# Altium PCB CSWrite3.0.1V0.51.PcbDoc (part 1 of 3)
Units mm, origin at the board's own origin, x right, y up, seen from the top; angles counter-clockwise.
Board outline 100 x 80 mm, 4 copper layers (Top Layer, power, gnd, Bottom Layer), stack 0.778 mm thick; 246 components, 181 nets, 873 pads, 864 vias.
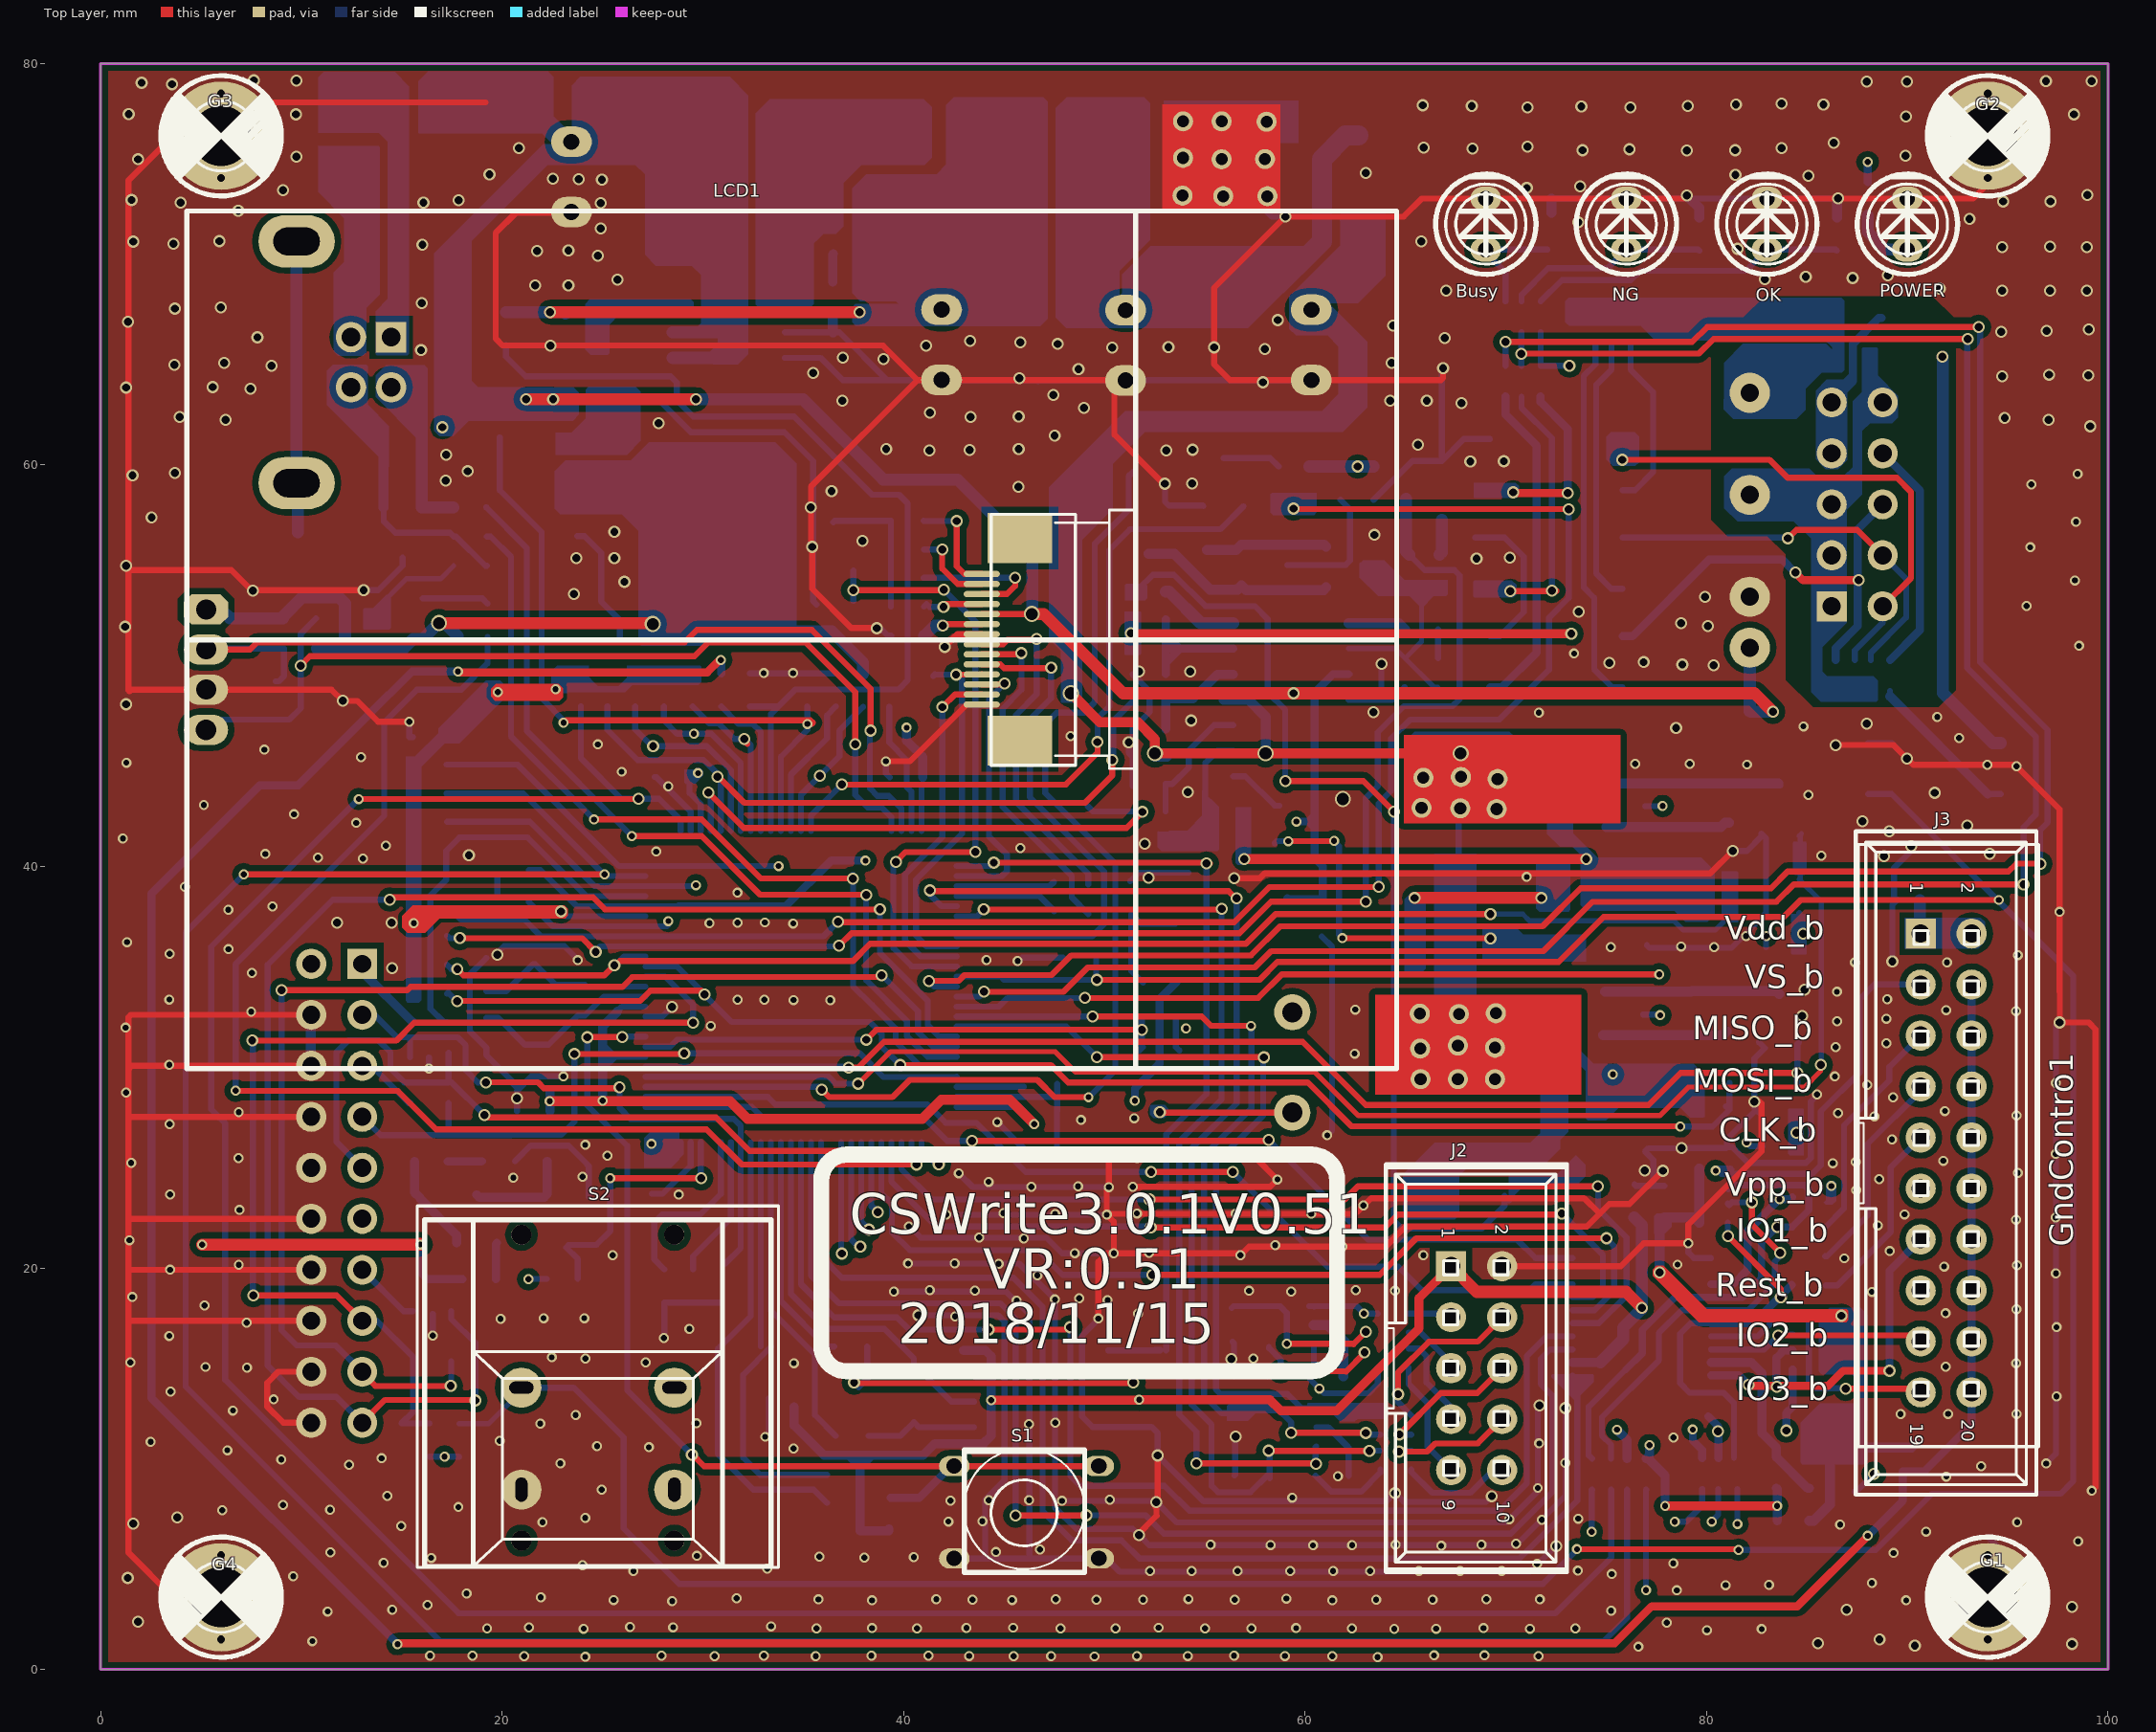
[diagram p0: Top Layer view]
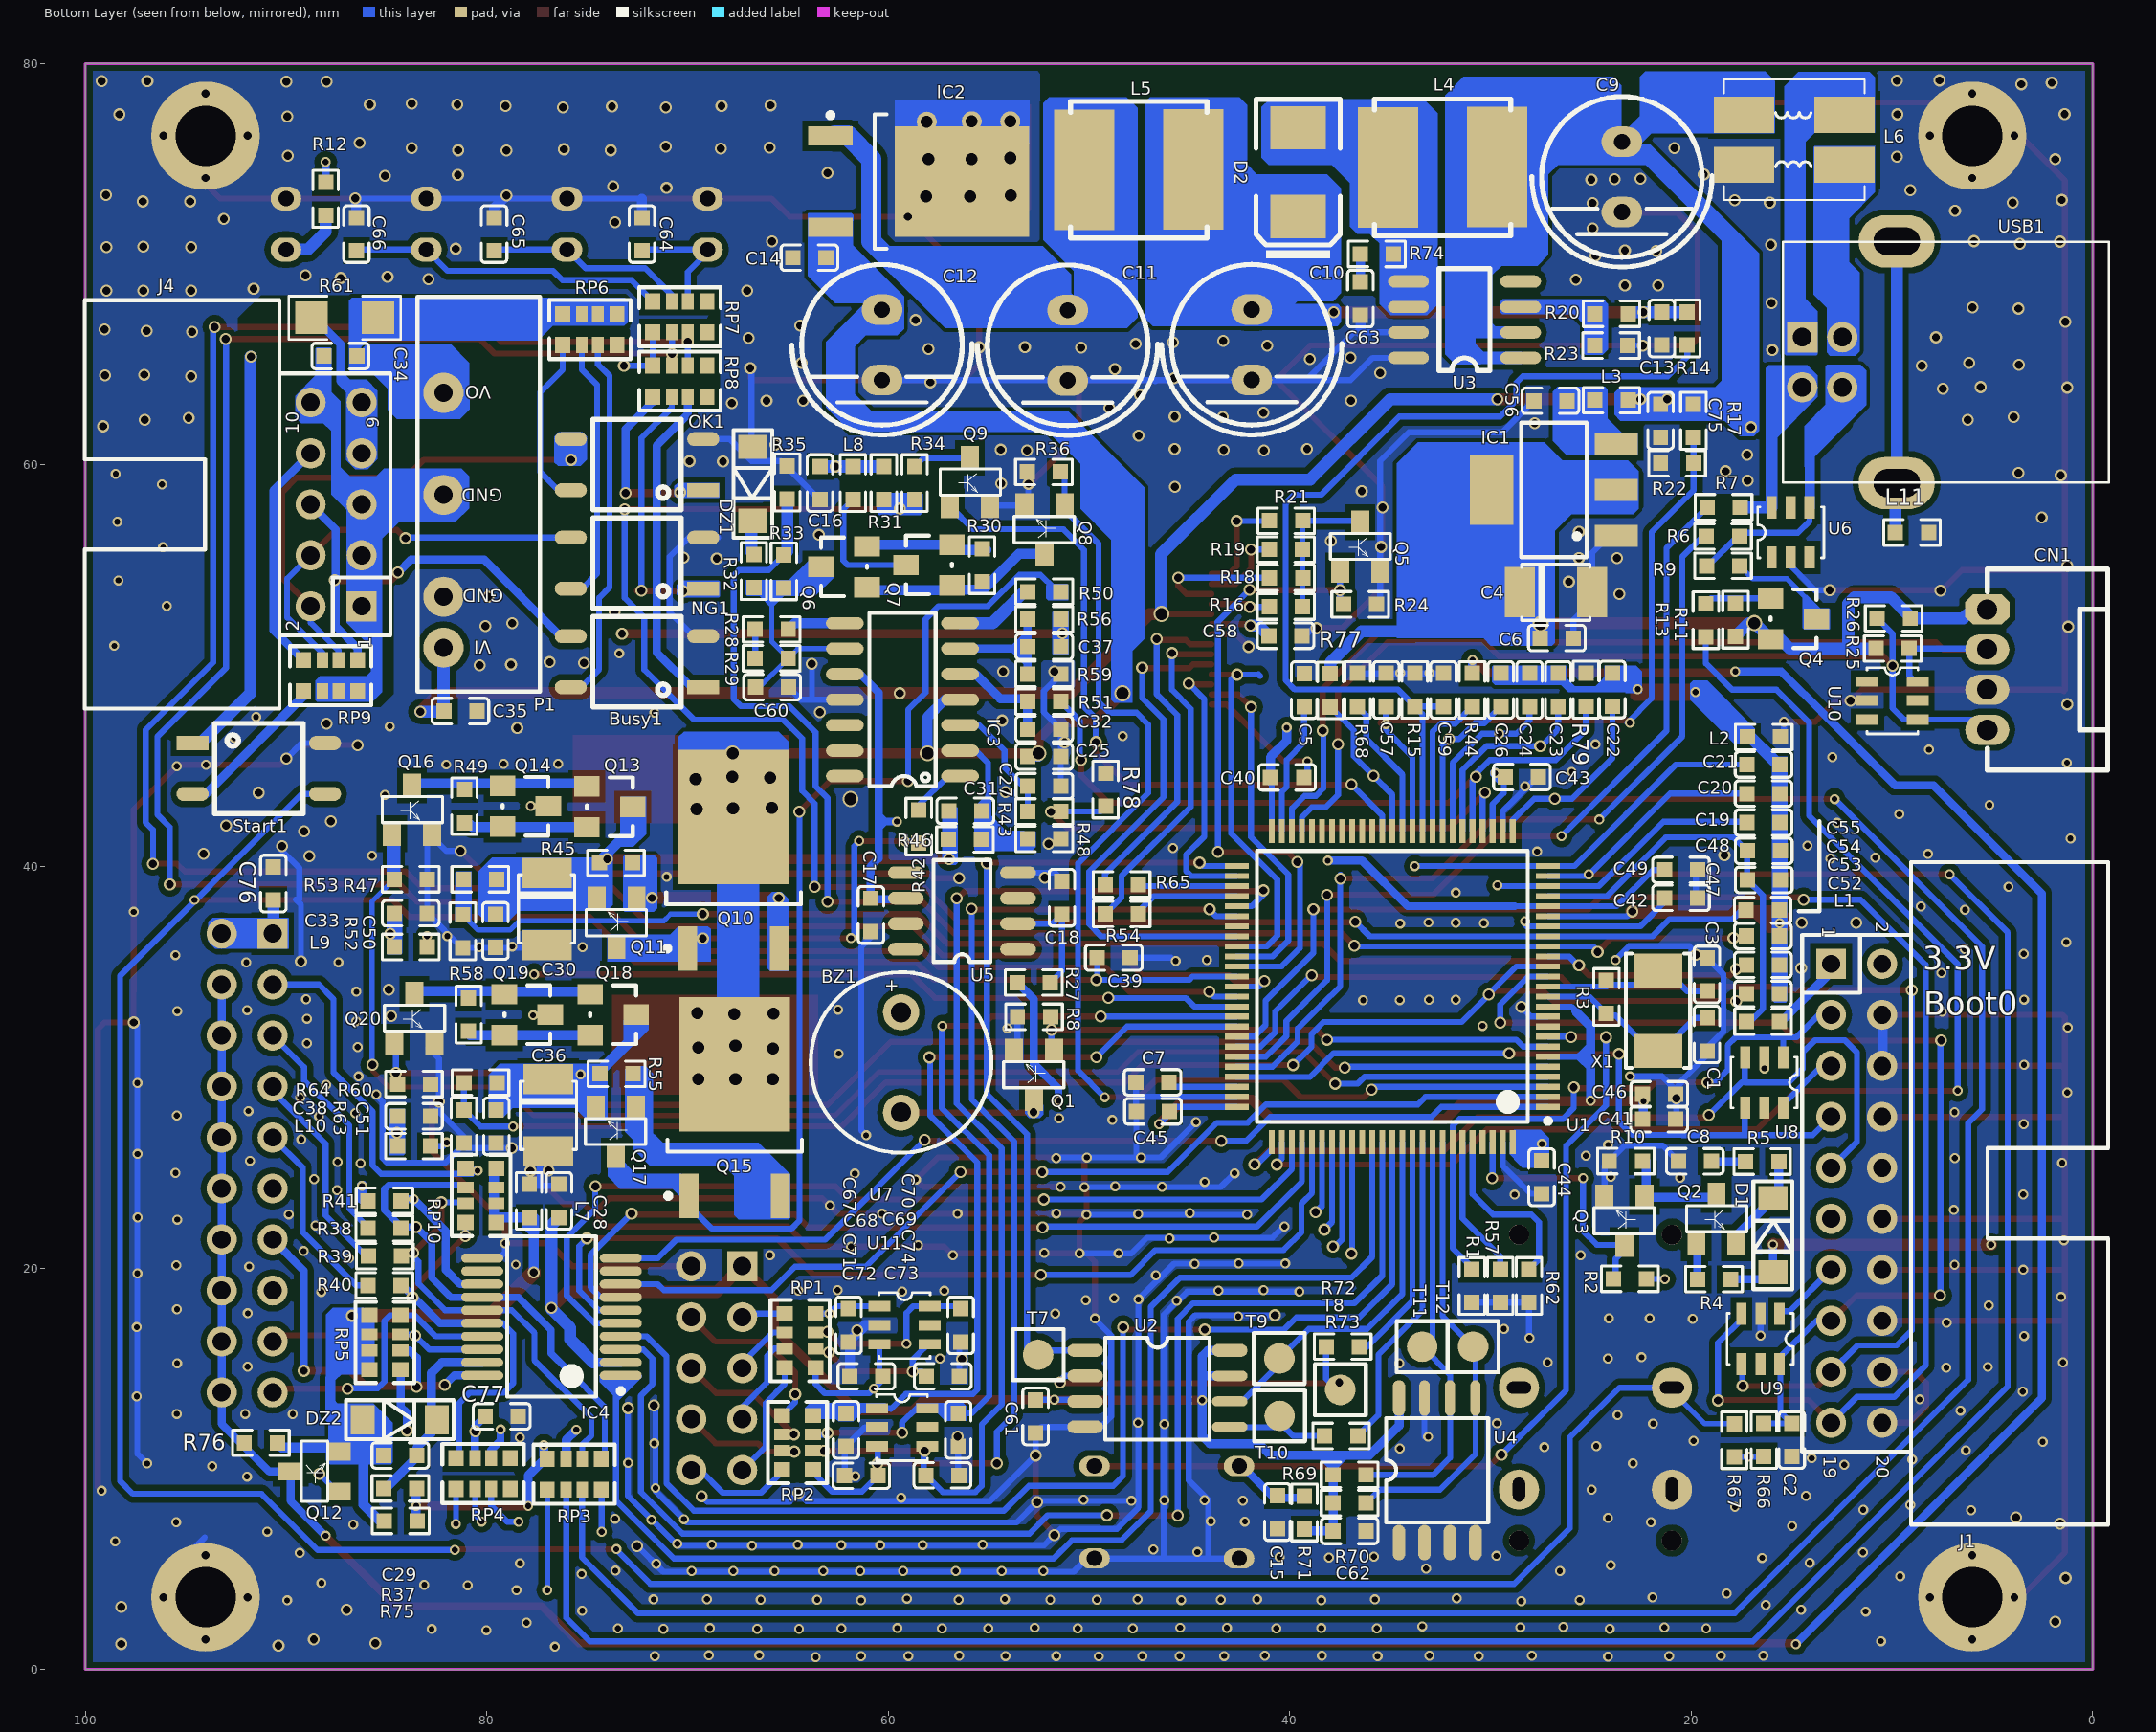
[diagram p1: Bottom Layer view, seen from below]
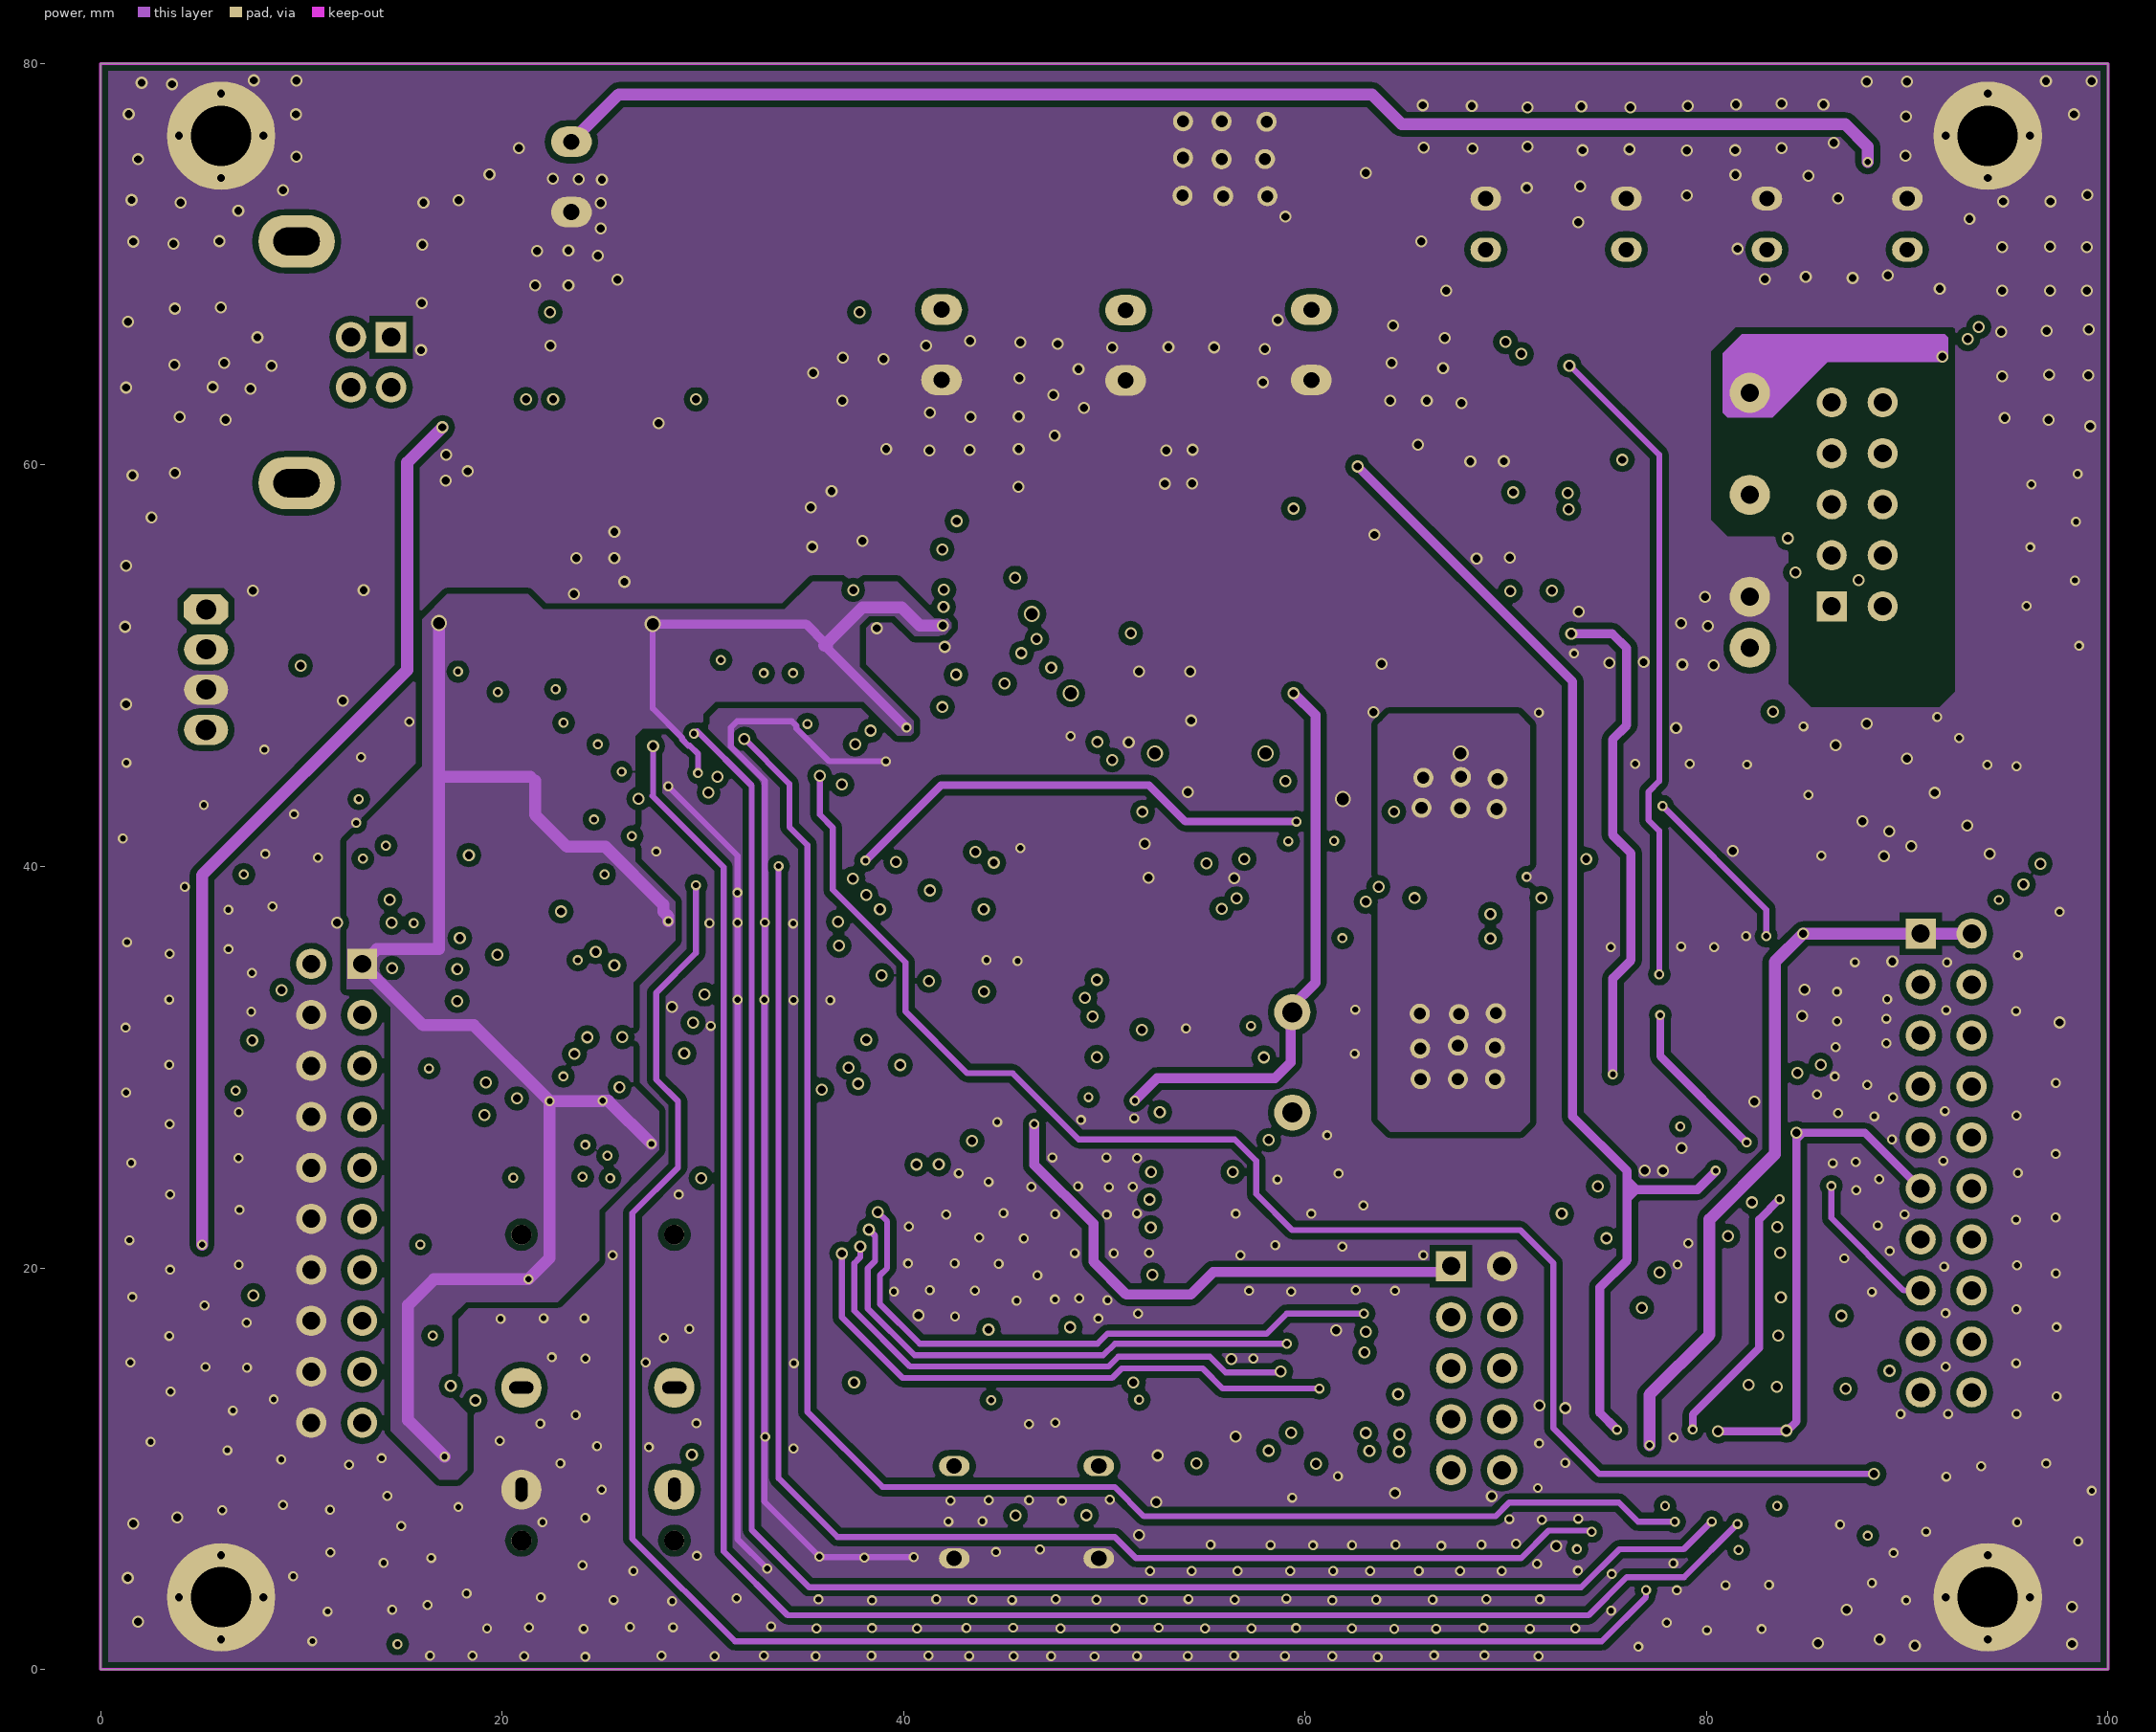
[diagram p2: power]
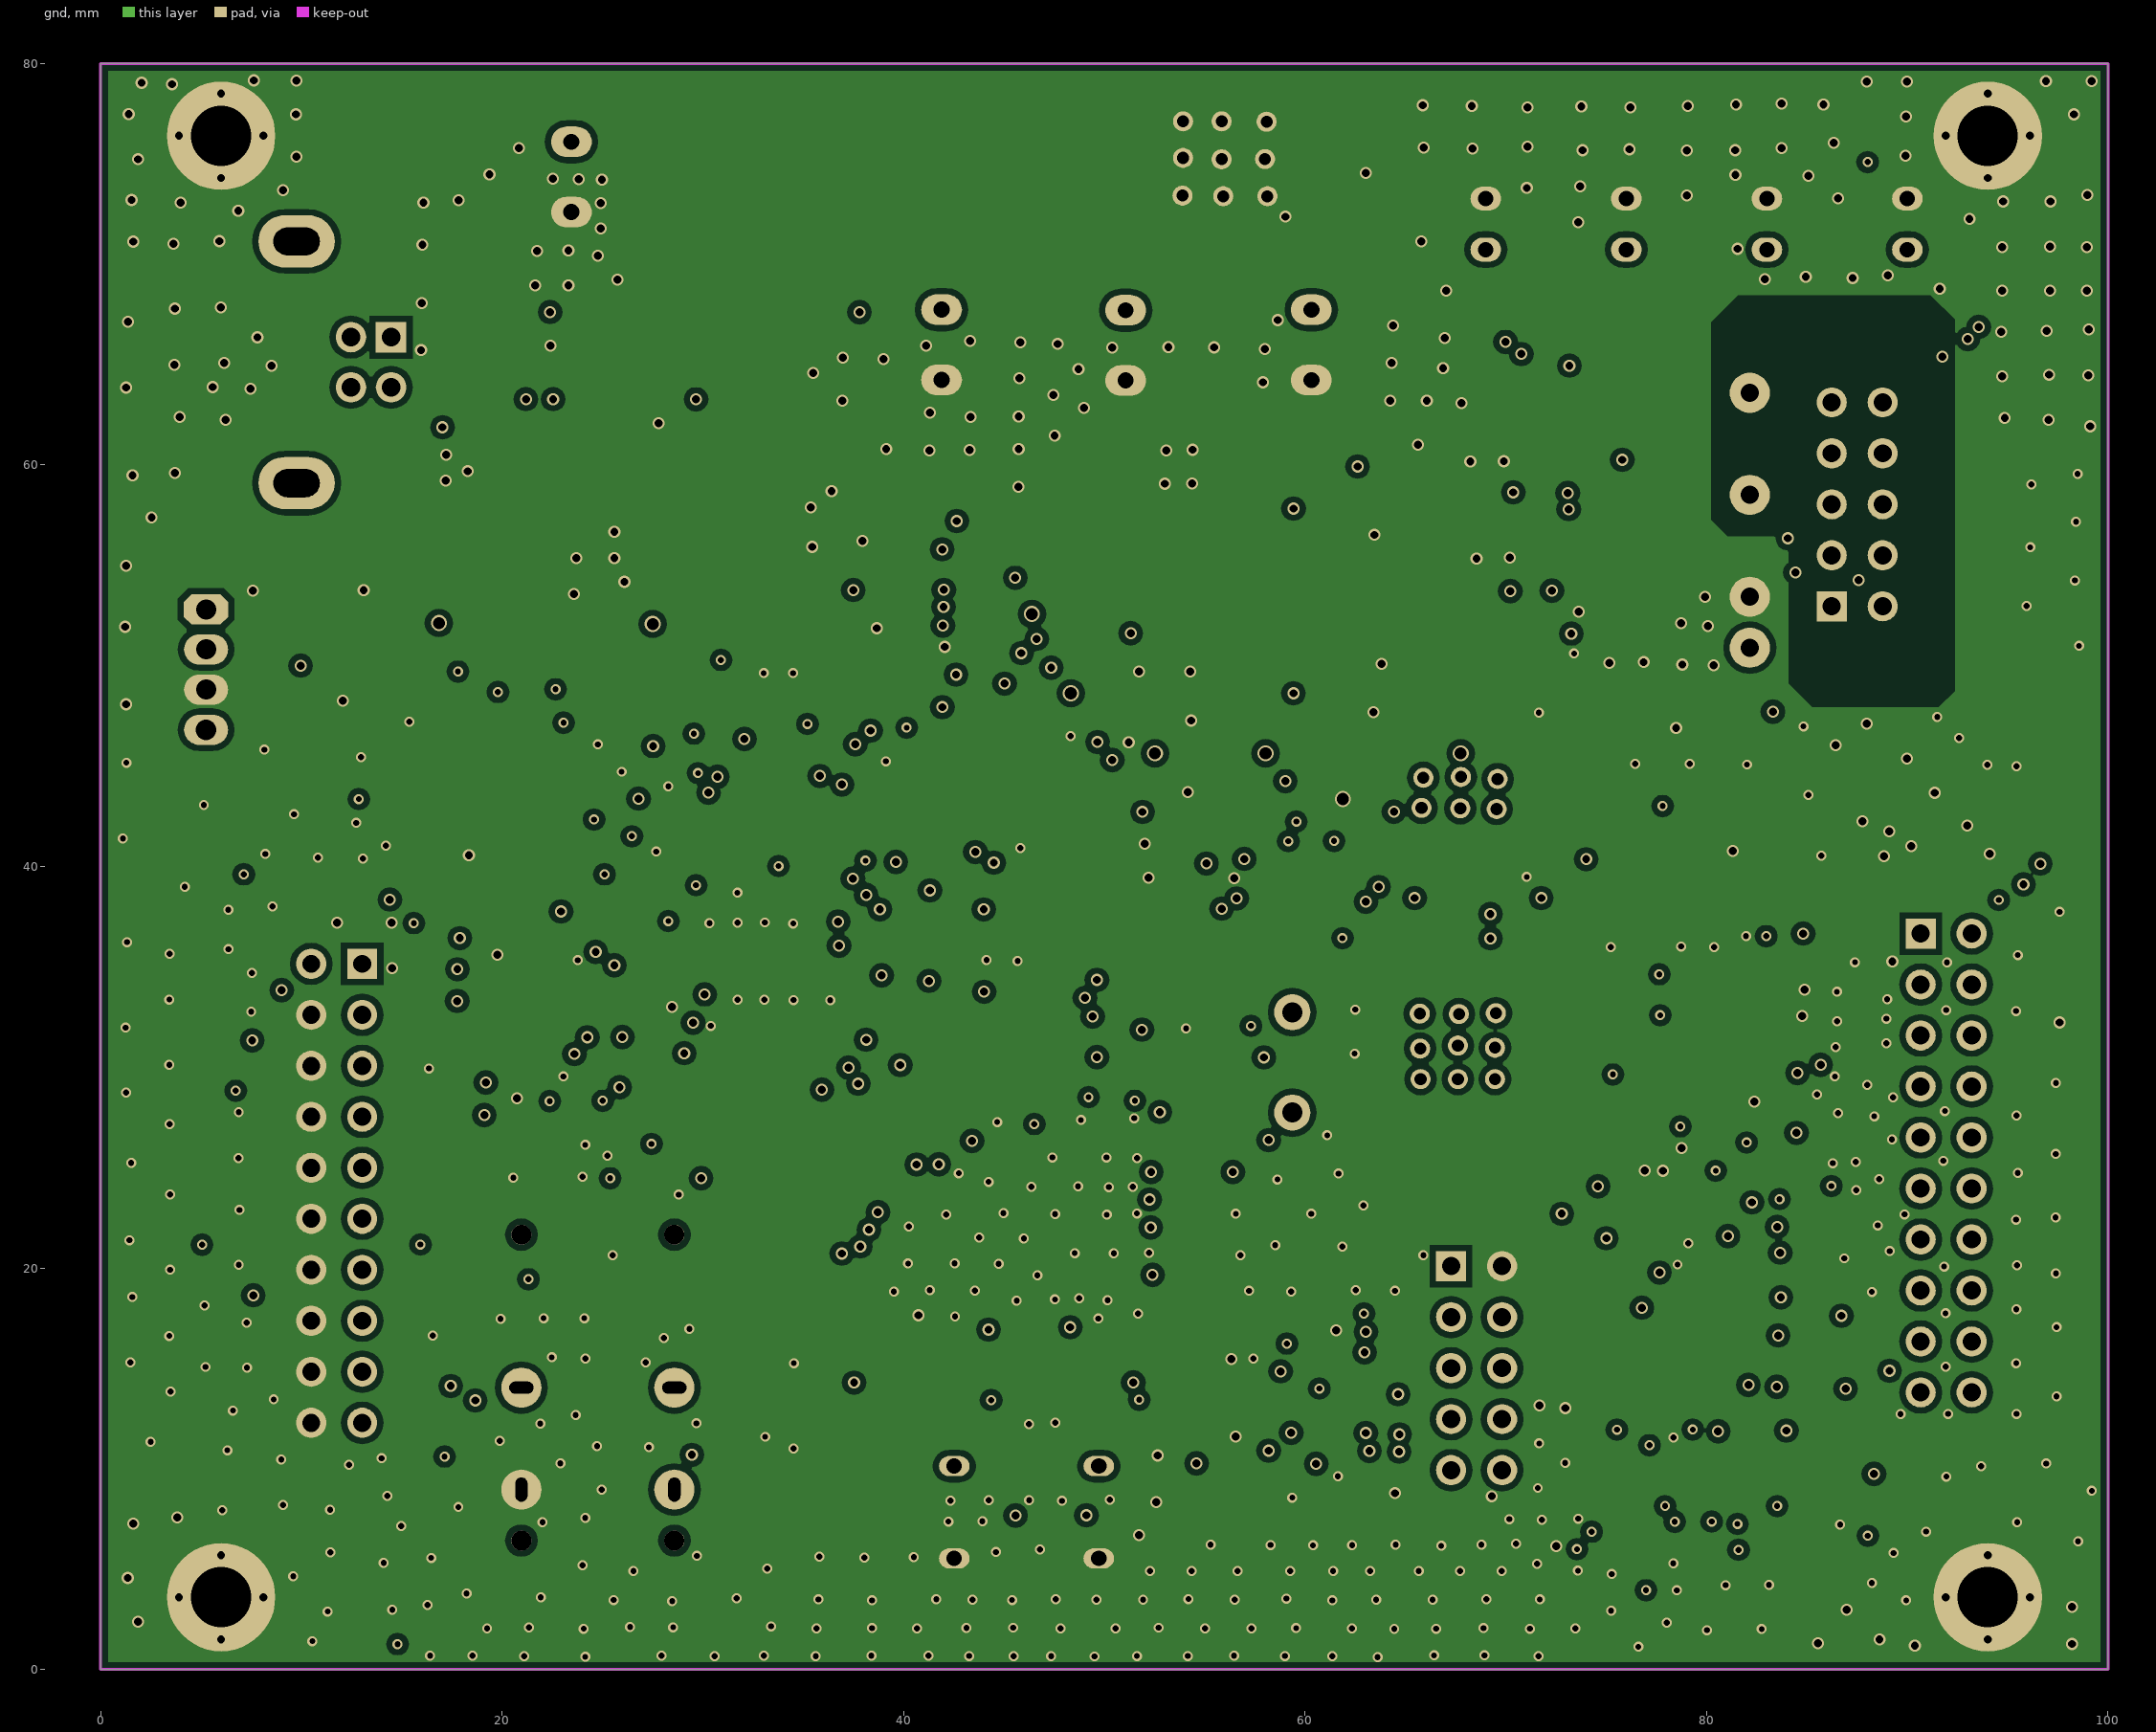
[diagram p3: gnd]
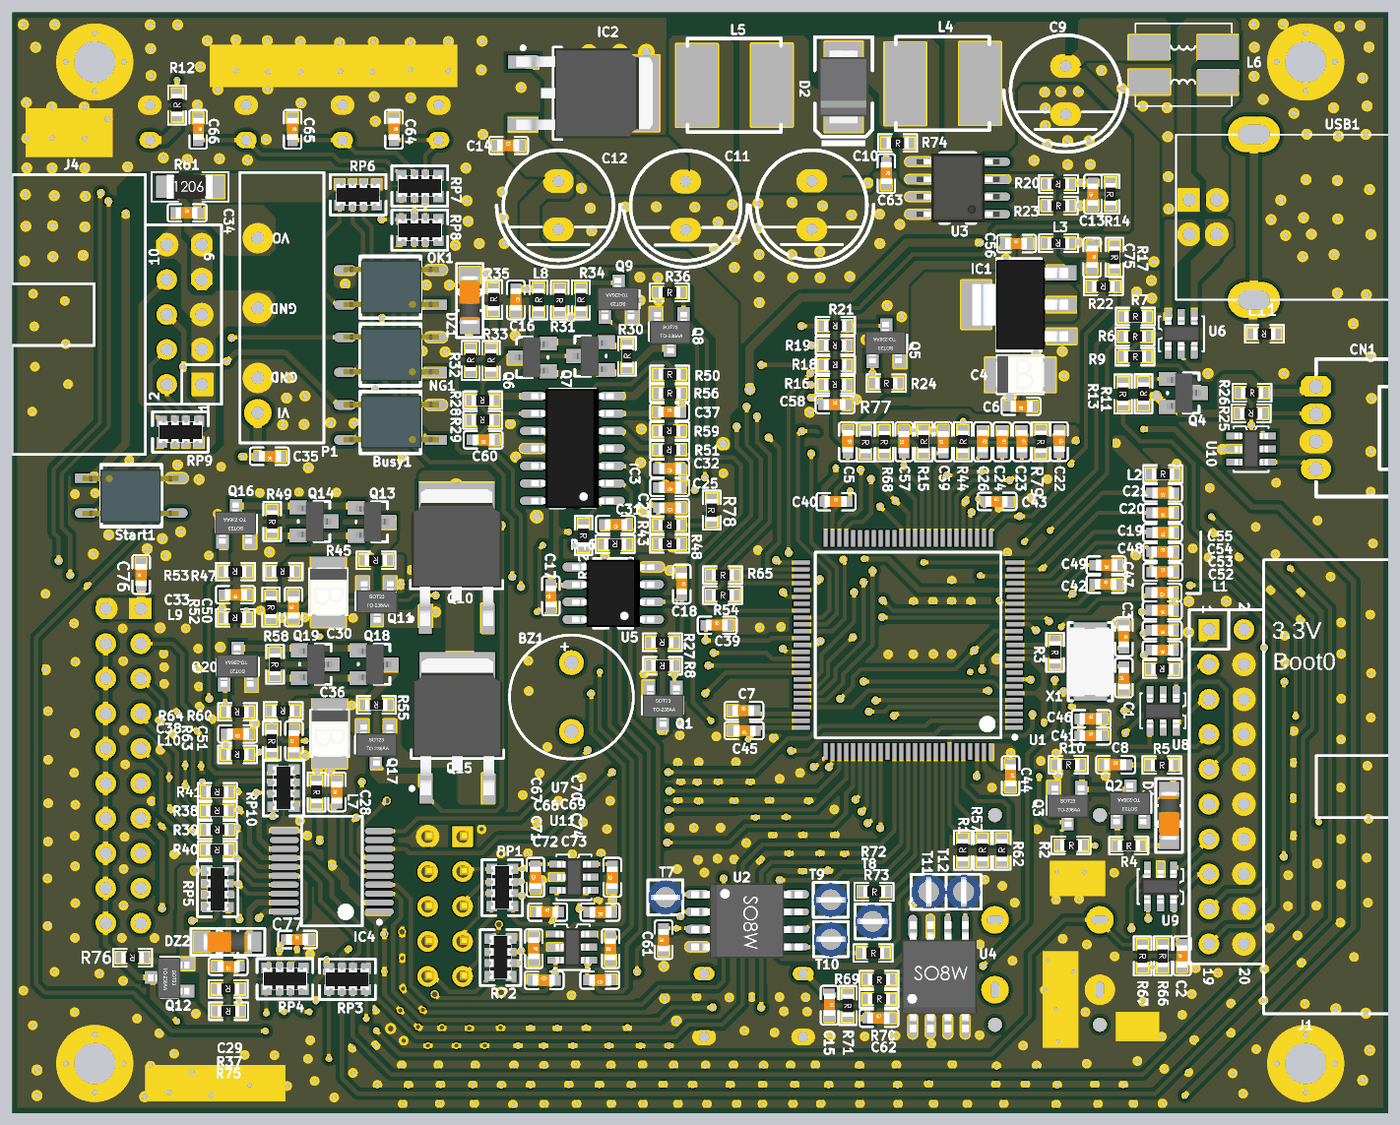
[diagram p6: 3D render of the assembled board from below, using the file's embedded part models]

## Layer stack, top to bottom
Top Solder: solder mask 0.0102, Solder Resist, Dk 3.5
Top Layer: signal copper 0.0356
Dielectric1: core 0.254, FR-4, Dk 4.2
power: signal copper 0.036
Dielectric 3: prepreg 0.127, Dk 4.2
gnd: signal copper 0.036
Dielectric 2: core 0.254, Dk 4.2
Bottom Layer: signal copper 0.0356
Bottom Solder: solder mask 0.0102, Solder Resist, Dk 3.5

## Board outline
0,0 100,0 100,80 0,80

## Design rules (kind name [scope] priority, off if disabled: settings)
Clearance [All] p1: gap=0.15 ignorepadtopadclearanceinfootprint=FALSE except(0: Arc-Hole Track-Hole SMDPad-Hole THPad-Hole Via-Hole Fill-Hole Poly-Hole Region-Hole Text-Hole; 0.2: Arc-Region Track-Region SMDPad-Region THPad-Region Via-Region Fill-Region Poly-Region Region-Region; 0.3: Arc-Poly Track-Poly SMDPad-Poly THPad-Poly Via-Poly Fill-Poly Poly-Poly)
ComponentClearance [All] p1 off: gap=0 collisioncheckmode=3 verticalgap=0 showdistances=FALSE
HoleSize [All] p1: absolutevalues=TRUE maxlimit=7.5 minlimit=0.025 maxpercent=80.000 minpercent=20.000
HoleToHoleClearance [All] p1: gap=0 allowstackedmicrovias=TRUE
MinimumSolderMaskSliver [All] p1: minsoldermaskwidth=0
PlaneConnect [All] p1: planeconnectstyle=Direct reliefexpansion=0.508 reliefentries=4 reliefconductorwidth=0.254 reliefairgap=0.254
PolygonConnect [All] p1: connectstyle=Direct reliefconductorwidth=0.254 reliefentries=4 polygonreliefangle="45 Angle" airgapwidth=0.254
RoutingVias RoutingVias_1 [All] p1: holewidth=0.711 width=1.27 viastyle="Through Hole" minholewidth=0.3 minwidth=0.5 maxholewidth=0.711 maxwidth=1.27
RoutingVias [All] p2: holewidth=0.6 width=1 viastyle="Through Hole" minholewidth=0.4 minwidth=0.6 maxholewidth=10 maxwidth=10
SilkToSilkClearance [All] p1: silktosilkclearance=0
SilkToSolderMaskClearance SilkscreenOverComponentPads [IsPad] p1: minsilkscreentomaskgap=0 clearancetoexposedcopper=TRUE
SolderMaskExpansion [All] p1: expansion=0.102
Width [All] p1: maxlimit=10 minlimit=0.254 preferedwidth=0.4
23 further rules are at their usual default settings.

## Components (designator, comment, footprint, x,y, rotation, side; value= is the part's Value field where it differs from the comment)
Busy "LED-R" LED05#1 69,72 r270 top locked
Busy1 "EL357" SOP-4 72.51,50.2 r90 bottom
BZ1 "BUZZER" FMQ-9*5.5 59.36,30.24 r270 bottom
C1 "20pF" 0603C 19.214,31.634 r90 bottom
C2 "104" 0603C 14.986,11.43 r90 bottom
C3 "20pF" 0603C 19.214,34.619 r270 bottom
C4 "100uF/16V" CAP-B 26.74,53.66 r180 bottom
C5 "225/6.3V" 0603C 39.279,48.79 r270 bottom
C6 "104/16V" 0603C 26.69,51.38 r0 bottom
C7 "225/6.3V" 0603C 46.83,29.25 r180 bottom
C8 "106/16V" 0603C 19.817,25.318 r180 bottom
C9 "100uF/16V" CB_8*11D5 23.44,74.35 r270 bottom
C10 "100uF/16V" CB_8*11D5 41.88,65.99 r270 bottom
C11 "100uF/16V" CB_8*11D5 51.05,65.96 r270 bottom
C12 "100uF/16V" CB_8*11D5 60.3,65.983 r270 bottom
C13 "104" 0603C 21.463,66.802 r90 bottom
C14 "104" 0603C 63.924,70.33 r180 bottom
C15 "103" 0603C 40.61,7.84 r270 bottom
C16 "102" 0603C 63.4,59.1 r270 bottom
C17 "104" 0603C 60.86,37.59 r90 bottom
C18 "104" 0603C 51.346,38.447 r270 bottom
C19 "102" 0603C 16.394,42.189 r0 bottom
C20 "102" 0603C 16.394,43.633 r0 bottom
C21 "102" 0603C 16.394,45.078 r0 bottom
C22 "102" 0603C 23.926,48.811 r270 bottom
C23 "102" 0603C 26.627,48.794 r270 bottom
C24 "102" 0603C 28.055,48.794 r270 bottom
C25 "104" 0603C 52.226,45.478 r0 bottom
C26 "102" 0603C 29.482,48.794 r270 bottom
C27 "104" 0603C 52.22,44 r0 bottom
C28 "104" 0603C 76.4,23.34 r90 bottom
C29 "104" 0603C 84.3,10.66 r0 bottom
C30 "100uF/16V" CAP-B 77.021,37.883 r270 bottom
C31 "20pF" 0603C 56.158,42.772 r0 bottom
C32 "104" 0603C 52.226,46.847 r0 bottom
C33 "102" 0603C 83.784,37.675 r0 bottom
C34 "10uF/16V" 0603C 87.29,65.43 r180 bottom
C35 "4.7uF/16V" 0603C 81.31,47.74 r0 bottom
C36 "100uF/16V" CAP-B 76.93,27.6 r270 bottom
C37 "20pF" 0603C 52.226,50.953 r180 bottom
C38 "102" 0603C 83.62,27.555 r0 bottom
C39 "103" 0603C 48.764,35.46 r180 bottom
C40 "104" 0603C 40.13,44.44 r180 bottom
C41 "104" 0603C 21.599,27.413 r180 bottom
C42 "104" 0603C 20.506,38.439 r180 bottom
C43 "104" 0603C 28.43,44.457 r180 bottom
C44 "104" 0603C 27.451,24.52 r270 bottom
C45 "104" 0603C 46.81,27.8 r0 bottom
C46 "104" 0603C 21.59,28.65 r180 bottom
C47 "104" 0603C 16.383,39.332 r180 bottom
C48 "225" 0603C 16.383,40.776 r180 bottom
C49 "104" 0603C 20.506,39.829 r0 bottom
C50 "104" 0603C 79.56,36.79 r90 bottom
C51 "104" 0603C 79.52,27.05 r90 bottom
C52 "103" 0603C 16.427,33.656 r0 bottom
C53 "103" 0603C 16.427,35.1 r0 bottom
C54 "103" 0603C 16.427,36.544 r0 bottom
C55 "103" 0603C 16.437,37.831 r0 bottom
C56 "106/16V" 0603C 27.01,63.2 r180 bottom
C57 "103" 0603C 35.193,48.794 r90 bottom
C58 "104" 0603C 40.208,51.495 r180 bottom
C59 "103" 0603C 32.338,48.794 r90 bottom
C60 "106/16V" 0603C 65.782,48.934 r0 bottom
C61 "104" 0603C 52.66,12.605 r90 bottom
C62 "104" 0603C 37.014,6.902 r180 bottom
C63 "472" 0603C 36.48,68.29 r270 bottom
C64 "102" 0603C 72.263,71.501 r270 bottom
C65 "102" 0603C 79.629,71.501 r270 bottom
C66 "102" 0603C 86.487,71.501 r270 bottom
C67 "102" 0603C 61.976,17.145 r90 bottom
C68 "102" 0603C 61.087,14.605 r180 bottom
C69 "102" 0603C 57.277,14.605 r0 bottom
C70 "102" 0603C 56.388,17.145 r90 bottom
C71 "102" 0603C 62.103,11.938 r270 bottom
C72 "102" 0603C 61.341,9.652 r180 bottom
C73 "102" 0603C 57.3,9.67 r0 bottom
C74 "102" 0603C 56.515,11.938 r90 bottom
C75 "104" 0603C 21.526,62.205 r270 bottom
C76 "104" 0603C 90.628,39.15 r90 bottom
C77 "104" 0603C 79.251,12.61 r180 bottom
CN1 "温度插座" PH4AW_2D0 5.25,49.81 r270 bottom
D1 "4148" D1206 15.93,21.63 r270 bottom
D2 "SS34" D-SMA 39.58,74.59 r90 bottom
DZ1 "6V" D1206 66.74,59.06 r90 bottom
DZ2 "5V6" D1206 84.328,12.446 r0 bottom
G1 "GND" P1 94,3.6 r0 top
G2 "GND" P1 94,76.4 r0 top
G3 "GND" P1 6,76.4 r0 top
G4 "GND" P1 6,3.6 r0 top
IC1 "LD1117-3.3" SOT223 26.84,58.76 r90 bottom
IC2 "7812" TO252AA 59.6,74.12 r0 bottom
IC3 "LM324R" SOP14 59.29,48.31 r90 bottom
IC4 "TXB0108PWR" TSSOP20 76.77,17.57 r90 bottom
J1 "调试口" DC_20P_W 11.76,23.72 r270 bottom locked
J2 "扩展口" IDC10-GZ 68.54,15.01 r270 top
J3 "烧录口" IDC20 91.93,25.23 r270 top locked
J4 "机台控制" DC_10P_W 87.5,58.04 r90 bottom locked
L1 "100M 100R 3A" 0603 16.42,32.27 r0 bottom
L2 "100M 100R 3A" 0603 16.385,46.451 r180 bottom
L3 "100M 100R 3A" 0603 23.97,63.23 r0 bottom
L4 "47uH" L-SMD6.8*6.8 32.385,74.828 r180 bottom
L5 "47uH" L-SMD6.8*6.8 47.52,74.71 r180 bottom
L6 "ACM4520" L_6*7 14.87,76.2 r180 bottom
L7 "100M 100R 3A" 0603 77.89,23.34 r270 bottom
L8 "100M 100R 3A" 0603 61.755,59.1 r90 bottom
L9 "100M 100R 3A" 0603 83.784,35.991 r0 bottom
L10 "100M 100R 3A" 0603 83.62,26.07 r0 bottom
L11 "100M 100R 3A" 0603 9,56.64 r0 bottom
LCD1 "TM024HDH26" TM024HDH26-V02 44.84,51.32 r0 top locked
NG "LED-R" LED05#1 76,72 r270 top locked
NG1 "EL357" SOP-4 72.51,55.11 r90 bottom
OK "LED-G" LED05#1 83,72 r270 top locked
OK1 "EL357" SOP-4 72.51,60.02 r90 bottom
P1 "DCDC1W" 1WDC_DC-4 82.15,57.246 r90 bottom
POWER "R" LED05#2 90,72 r180 top locked
Q1 "SI2300" SOT-23 52.734,29.63 r90 bottom
Q2 "S8550" SOT-23 18.74,22.45 r270 bottom
Q3 "SI2300" SOT-23 23.32,22.35 r90 bottom
Q4 "S8550" SOT23 14.9,52.34 r0 bottom
Q5 "SI2300" SOT-23 36.488,55.945 r270 bottom
Q6 "SI2301" SOT23 62.2,54.93 r180 bottom
Q7 "SI2301" SOT23 57.97,55.02 r180 bottom
Q8 "SI2300" SOT-23 52.211,56.783 r90 bottom
Q9 "SI2300" SOT-23 55.93,59.15 r270 bottom
Q10 "D882M" TO252AA 67.7,39.19 r270 bottom
Q11 "9014" SOT-23 73.531,37.203 r90 bottom
Q12 "SI2300" SOT-23 88.57,9.86 r180 bottom
Q13 "SI2301" SOT23 73.871,42.973 r0 bottom
Q14 "SI2301" SOT23 78.071,43.003 r0 bottom
Q15 "D882M" TO252AA 67.65,26.865 r270 bottom
Q16 "SI2300" SOT-23 83.72,42.83 r270 bottom
Q17 "9014" SOT-23 73.564,26.795 r90 bottom
Q18 "SI2301" SOT23 73.7,32.62 r0 bottom
Q19 "SI2301" SOT23 77.976,32.62 r0 bottom
Q20 "SI2300" SOT-23 83.606,32.445 r270 bottom
R1 "10K" 0603 30.927,19.102 r90 bottom
R2 "100K" 0603 23.05,19.46 r180 bottom
R3 "1M" 0603 24.22,33.5 r270 bottom
R4 "10K" 0603 18.86,19.44 r180 bottom
R5 "1K" 0603 16.46,25.3 r180 bottom
R6 "22R" 0603 18.414,56.438 r180 bottom
R7 "22R" 0603 18.384,57.898 r180 bottom
R8 "100K" 0603 52.734,32.512 r0 bottom
R9 "1K5" 0603 18.41,54.98 r180 bottom
R10 "100K" 0603 23.251,25.324 r180 bottom
R11 "10K" 0603 17.79,52.29 r90 bottom
R12 "10K" 0603 88.02,73.26 r90 bottom
R13 "1K" 0603 19.27,52.27 r270 bottom
R14 "10K" 0603 20.193,66.802 r270 bottom
R15 "1K" 0603 33.766,48.794 r90 bottom
R16 "100" 0603 40.188,52.945 r0 bottom
R17 "10K" 0603 19.887,62.203 r270 bottom
R18 "100" 0603 40.178,54.375 r0 bottom
R19 "100" 0603 40.188,55.795 r0 bottom
R20 "22K" 0603 23.967,67.533 r0 bottom
R21 "100" 0603 40.178,57.225 r0 bottom
R22 "1K" 0603 20.701,60.09 r0 bottom
R23 "2K" 0603 23.987,65.953 r180 bottom
R24 "100K" 0603 36.488,53.055 r180 bottom
R25 "10K" 0603 9.96,50.86 r0 bottom
R26 "10K" 0603 9.91,52.36 r180 bottom
R27 "10R" 0603 52.75,34.22 r0 bottom
R28 "100" 0603 65.802,51.814 r0 bottom
R29 "100" 0603 65.802,50.374 r0 bottom
R30 "10K" 0603 55.32,55.01 r90 bottom
R31 "10K 1%" 0603 60.217,59.1 r270 bottom
R32 "10R" 0603 66.69,54.71 r90 bottom
R33 "1K 1%" 0603 65.2,54.7 r90 bottom
R34 "10K 1%" 0603 58.68,59.1 r90 bottom
R35 "1K 1%" 0603 65.03,59.13 r90 bottom
R36 "100K" 0603 52.241,59.653 r180 bottom
R37 "10R" 0603 84.3,9.02 r0 bottom
R38 "100R" 0603 85.1,21.98 r0 bottom
R39 "100R" 0603 85.076,20.592 r0 bottom
R40 "100R" 0603 85.096,19.132 r0 bottom
R41 "100R" 0603 85.087,23.343 r0 bottom
R42 "1K" 0603 58.48,41.985 r270 bottom
R43 "1K" 0603 52.226,42.741 r0 bottom
R44 "100k" 0603 30.91,48.794 r90 bottom
R45 "7.5R" 0603 73.561,40.183 r0 bottom
R46 "3K 1%" 0603 56.178,41.352 r0 bottom
R47 "3K 1%" 0603 80.32,39.36 r0 bottom
R48 "1K 1%" 0603 52.226,41.372 r0 bottom
R49 "10K" 0603 81.11,43.003 r270 bottom
R50 "1K" 0603 52.226,53.69 r180 bottom
R51 "1K" 0603 52.226,48.215 r0 bottom
R52 "1K 1%" 0603 81.19,36.77 r270 bottom
R53 "100K" 0603 83.784,39.36 r0 bottom
R54 "0R" 0603 48.37,37.635 r180 bottom
R55 "10R" 0603 73.53,29.67 r0 bottom
R56 "3K 1%" 0603 52.226,52.321 r180 bottom
R57 "10K" 0603 29.506,19.102 r90 bottom
R58 "10K" 0603 80.9,32.62 r270 bottom
R59 "1K 1%" 0603 52.226,49.584 r0 bottom
R60 "3K 1%" 0603 80.31,29.23 r0 bottom
R61 "100" 1206 87.07,67.33 r180 bottom
R62 "10K" 0603 28.086,19.102 r90 bottom
R63 "1K 1%" 0603 81.13,27.05 r270 bottom
R64 "100K" 0603 83.62,29.16 r0 bottom
R65 "0R" 0603 48.37,39.1 r180 bottom
R66 "10K" 0603 16.383,11.43 r270 bottom
R67 "10K" 0603 17.855,11.417 r270 bottom
R68 "10K" 0603 36.621,48.794 r270 bottom
R69 "10K" 0603 37.014,9.696 r180 bottom
R70 "10K" 0603 37.014,8.299 r180 bottom
R71 "10K" 0603 39.27,7.82 r270 bottom
R72 "0R" 0603 37.36,16.082 r180 bottom
R73 "0R" 0603 37.435,11.637 r180 bottom
R74 "10R" 0603 35.66,70.51 r180 bottom
R75 "12K" 0603 84.28,7.4 r0 bottom
R76 "100K" 0603 91.25,11.29 r0 bottom
R77 "100K" 0603 37.981,48.77 r270 bottom
R78 "1M" 0603 49.17,43.83 r270 bottom
R79 "1M" 0603 25.24,48.81 r270 bottom
RP1 "100R" 0603_RX4 64.389,16.383 r90 bottom
RP2 "100R" 0603_RX4 64.516,11.303 r270 bottom
RP3 "100K" 0603_RX4 75.64,9.73 r180 bottom
RP4 "100K" 0603_RX4 80.18,9.76 r180 bottom
RP5 "12K" 0603_RX4 85.066,16.292 r270 bottom
RP6 "1K" 0603_RX4 74.86,66.75 r0 bottom
RP7 "1K" 0603_RX4 70.38,67.38 r180 bottom
RP8 "1K" 0603_RX4 70.38,64.18 r0 bottom
RP9 "1K" 0603_RX4 87.78,49.51 r180 bottom
RP10 "12K" 0603_RX4 80.28,23.615 r90 bottom
S1 "SW-PB" SW6*6 46.12,7.83 r0 top locked
S2 "SW-PB" SW12*17_PB86 24.77,11.5 r0 top locked
Start1 "EL357" SOP-4 91.35,44.88 r270 bottom
T7 "GND" P2 52.53,15.68 r90 bottom
T8 "GND" P2 37.48,13.93 r90 bottom
T9 "GND" P2 40.513,15.494 r90 bottom
T10 "GND" P2 40.5,12.63 r90 bottom
T11 "GND" P2 33.4,16.08 r0 bottom
T12 "GND" P2 30.861,16.082 r0 bottom
U1 "STM32F407VET6" LQFP100_V 34.887,34.022 r0 bottom
U2 "W25X64" SO-08M 46.587,13.99 r270 bottom
U3 "XL6007" SO-8 31.29,67.24 r90 bottom
U4 "MB85RC16PNF" SO-08M 32.65,9.92 r180 bottom
U5 "ADR03" SOP8 56.326,37.787 r90 bottom
U6 "BST236A054U" SOT-23-6L 15.05,56.64 r180 bottom
U7 "BST236A054U" SOT-23-6L 59.182,17.145 r270 bottom
U8 "BST236A054U" SOT-23-6L 16.36,29.24 r0 bottom
U9 "BST236A054U" SOT-23-6L 16.55,16.47 r0 bottom
U10 "BST236A054U" SOT-23-6L 9.97,48.27 r270 bottom
U11 "BST236A054U" SOT-23-6L 59.309,12.065 r270 bottom
USB1 "USB2" USB2*2 13.47,65.12 r270 bottom locked
X1 "8MHz" ATX5*3.2 21.65,32.81 r270 bottom

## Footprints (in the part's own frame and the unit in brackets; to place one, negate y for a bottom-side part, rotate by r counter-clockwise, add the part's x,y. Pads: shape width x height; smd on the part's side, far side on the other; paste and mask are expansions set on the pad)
1WDC_DC-4 [mm]
  round 2 hole 0.9: 1(-6.35,0) 2(-3.81,0) 3(1.27,0) 4(6.35,0)
  silkscreen extent -8.53,-4.8 11.13,1.3
0603 [mil]
  rect 30x30 smd: 1(-32.5,0) 2(32.5,0)
  silkscreen extent -56,-25 56,25, body extent -51,-20 52,20, height 21
0603_RX4 [mm]
  rect 0.75x0.8 smd mask+0.051: 1(-1.35,-0.77) 4(1.35,-0.77) 5(1.35,0.77) 8(-1.35,0.77)
  rect 0.58x0.8 smd mask+0.051: 2(-0.4,-0.77) 3(0.4,-0.77) 6(0.4,0.77) 7(-0.4,0.77)
  silkscreen extent -2.03,-1.47 2.03,1.47, body extent -1.6,-0.8 1.6,0.8, height 0.55
0603C [mil]
  rect 30x30 smd: 1(-32.5,0) 2(32.5,0)
  silkscreen extent -56,-25 56,25, body extent -33,-15 30,16, height 12
1206 [mil] "1206"
  rect 64x64 smd: 1(-65,0) 2(65,0)
  silkscreen extent -110,-43 110,42, body extent -67,-34 65,34, height 33
ATX5*3.2 [mm] "晶振"
  rect 1.7x2.4 smd: 1(-2,0) 2(2,0)
  silkscreen extent -2.85,-1.6 2.85,1.6, body extent -2.48,-1.64 2.52,1.56, height 1.3
CAP-B [mm]
  rect 1.5x2.5 smd: 1(-1.8,0) 2(1.8,0)
  silkscreen extent -1.7,-1.4 1.7,1.4, body extent -1.77,-1.38 1.73,1.42, height 1.9
CB_8*11D5 [mm]
  oval 1.524x2.032 hole 0.8: 1(-1.75,-0.01) 2(1.75,-0.01)
  silkscreen extent -4,-4.5 4.49,4.48
D1206 [mm]
  rect 1.2x1.45 smd: 1(1.842,0) 2(-1.842,0)
  silkscreen extent -2.68,-0.97 2.68,0.97, body extent -1.72,-0.73 1.78,0.77, height 1.47
D-SMA [mil] "SS14"
  rect 85x107.99 smd: 1(87.01,0) 2(-87.01,0)
  silkscreen extent -169,-83 143,83, body extent -106,-71 106,71, height 91
DC_10P_W [mm]
  rect 1.5x1.5 hole 0.9: 1(-5.08,-1.27)
  round 1.5 hole 0.9: 2(-5.08,1.27) 3(-2.54,-1.27) 4(-2.54,1.27) 5(0,-1.27) 6(0,1.27) 7(2.54,-1.27) 8(2.54,1.27) 9(5.08,-1.27) 10(5.08,1.27)
  silkscreen extent -10.17,-2.71 10.17,12.53
DC_20P_W [mm]
  rect 1.5x1.5 hole 0.9: 1(-11.43,-1.27)
  round 1.5 hole 0.9: 2(-11.43,1.27) 3(-8.89,-1.27) 4(-8.89,1.27) 5(-6.35,-1.27) 6(-6.35,1.27) 7(-3.81,-1.27) 8(-3.81,1.27) 9(-1.27,-1.27) 10(-1.27,1.27) 11(1.27,-1.27) 12(1.27,1.27) 13(3.81,-1.27) 14(3.81,1.27) 15(6.35,-1.27) 16(6.35,1.27) 17(8.89,-1.27) 18(8.89,1.27) 19(11.43,-1.27) 20(11.43,1.27)
  silkscreen extent -16.5,-2.71 16.5,12.53
FMQ-9*5.5 [mm]
  round 1.8 hole 1: 1(-2.5,0) 2(2.5,0)
  silkscreen extent -4.5,-4.5 4.5,4.5
IDC10-GZ [mm] "IDC公座"
  rect 1.5x1.5 hole 0.9: 1(-5.08,-1.27)
  round 1.5 hole 0.9: 2(-5.08,1.27) 3(-2.54,-1.27) 4(-2.54,1.27) 5(0,-1.27) 6(0,1.27) 7(2.54,-1.27) 8(2.54,1.27) 9(5.08,-1.27) 10(5.08,1.27)
  silkscreen extent -10.17,-4.51 10.17,4.5, body extent -10.37,-4.52 10.23,4.28, height 9.1
IDC20 [mm]
  rect 1.5x1.5 hole 0.9: 1(-11.43,-1.27)
  round 1.5 hole 0.9: 2(-11.43,1.27) 3(-8.89,-1.27) 4(-8.89,1.27) 5(-6.35,-1.27) 6(-6.35,1.27) 7(-3.81,-1.27) 8(-3.81,1.27) 9(-1.27,-1.27) 10(-1.27,1.27) 11(1.27,-1.27) 12(1.27,1.27) 13(3.81,-1.27) 14(3.81,1.27) 15(6.35,-1.27) 16(6.35,1.27) 17(8.89,-1.27) 18(8.89,1.27) 19(11.43,-1.27) 20(11.43,1.27)
  silkscreen extent -16.52,-4.5 16.52,4.5
L-SMD6.8*6.8 [mm] "贴片电感"
  rect 3x6 smd: 1(2.718,0.012) 2(-2.718,-0.013)
  silkscreen extent -3.4,-3.4 3.4,3.4
L_6*7 [mm] "贴片公模"
  rect 3x1.8 smd: 1(-2.5,-1.25) 2(-2.5,1.25) 3(2.5,1.25) 4(2.5,-1.25)
  silkscreen extent -3.5,-3 3.5,3
LED05#1 [mil]
  oval 47.24x60 hole 30: 1(50,0) 2(-50,0)
  silkscreen extent -98,-98 98,98, body extent -97,-115 118,117, height 378
LED05#2 [mil]
  oval 60x47.24 hole 30: 1(0,50) 2(0,-50)
  silkscreen extent -98,-98 98,98, body extent -117,-97 115,118, height 378
LQFP100_V [mm] "Thin QFP, 100-Leads, Body 14x14mm, Pitch 0.5mm, ST Recommended"
  rect 1.2x0.3 smd: 1(-7.75,6) 2(-7.75,5.5) 3(-7.75,5) 4(-7.75,4.5) 5(-7.75,4) 6(-7.75,3.5) 7(-7.75,3) 8(-7.75,2.5) 9(-7.75,2) 10(-7.75,1.5) 11(-7.75,1) 12(-7.75,0.5) 13(-7.75,0) 14(-7.75,-0.5) 15(-7.75,-1) 16(-7.75,-1.5) 17(-7.75,-2) 18(-7.75,-2.5) 19(-7.75,-3) 20(-7.75,-3.5) 21(-7.75,-4) 22(-7.75,-4.5) 23(-7.75,-5) 24(-7.75,-5.5) 25(-7.75,-6) 51(7.75,-6) 52(7.75,-5.5) 53(7.75,-5) 54(7.75,-4.5) 55(7.75,-4) 56(7.75,-3.5) 57(7.75,-3) 58(7.75,-2.5) 59(7.75,-2) 60(7.75,-1.5) 61(7.75,-1) 62(7.75,-0.5) 63(7.75,0) 64(7.75,0.5) 65(7.75,1) 66(7.75,1.5) 67(7.75,2) 68(7.75,2.5) 69(7.75,3) 70(7.75,3.5) 71(7.75,4) 72(7.75,4.5) 73(7.75,5) 74(7.75,5.5) 75(7.75,6)
  rect 0.3x1.2 smd: 26(-6,-7.75) 27(-5.5,-7.75) 28(-5,-7.75) 29(-4.5,-7.75) 30(-4,-7.75) 31(-3.5,-7.75) 32(-3,-7.75) 33(-2.5,-7.75) 34(-2,-7.75) 35(-1.5,-7.75) 36(-1,-7.75) 37(-0.5,-7.75) 38(0,-7.75) 39(0.5,-7.75) 40(1,-7.75) 41(1.5,-7.75) 42(2,-7.75) 43(2.5,-7.75) 44(3,-7.75) 45(3.5,-7.75) 46(4,-7.75) 47(4.5,-7.75) 48(5,-7.75) 49(5.5,-7.75) 50(6,-7.75) 76(6,7.75) 77(5.5,7.75) 78(5,7.75) 79(4.5,7.75) 80(4,7.75) 81(3.5,7.75) 82(3,7.75) 83(2.5,7.75) 84(2,7.75) 85(1.5,7.75) 86(1,7.75) 87(0.5,7.75) 88(0,7.75) 89(-0.5,7.75) 90(-1,7.75) 91(-1.5,7.75) 92(-2,7.75) 93(-2.5,7.75) 94(-3,7.75) 95(-3.5,7.75) 96(-4,7.75) 97(-4.5,7.75) 98(-5,7.75) 99(-5.5,7.75) 100(-6,7.75)
  silkscreen extent -7.87,-6.75 6.75,6.82, body extent -7,-7 7,7, height 1.6
P1 [mm]
  round 0.6 hole 0.4: 1(-2.1,0) 1(0,-2.1) 1(0,2.1) 1(2.1,0)
  round 5.4 hole 3: 1(0,0)
  silkscreen extent -3,-3 3,3
P2 [mil] "测试针"
  round 60 smd: 1(0,0)
  silkscreen extent -50,-50 50,50, body extent -50,-50 50,50, height 192
PH4AW_2D0 [mm]
  oct 1.5x2.2 hole 1: 1(-3,0)
  oval 1.5x2.2 hole 1: 2(-1,0) 3(1,0)
  oval 1.5x2.2 hole 1.016: 4(3,0)
  silkscreen extent -5,0 5,6
SO-8 [mil] "CEM4435"
  oval 24x80 smd: 1(-75,-110) 2(-25,-110) 3(25,-110) 4(75,-110) 5(75,110) 6(25,110) 7(-25,110) 8(-75,110)
  silkscreen extent -100,-50 100,50, body extent -99,-120 99,118, height 63
SO-08M [mm]
  oval 0.635x1.778 smd: 1(-1.905,-3.6) 2(-0.635,-3.6) 3(0.635,-3.6) 4(1.905,-3.6) 8(-1.905,3.6)
  oval 0.5x1.778 smd: 5(1.905,3.6) 6(0.635,3.6)
  oval 0.52x1.778 smd: 7(-0.635,3.6)
  silkscreen extent -2.54,-2.6 2.54,2.6, body extent -2.71,-4.07 2.75,4.03, height 1.75
SOP8 [mil]
  oval 25x70 smd: 1(-75,-110) 2(-25,-110) 3(25,-110) 4(75,-110) 5(75,110) 6(25,110) 7(-25,110) 8(-75,110)
  silkscreen extent -100,-56 100,56, body extent -97,-118 96,118, height 61
SOP14 [mil]
  oval 24x74 smd: 1(-150,-113) 2(-100,-113) 3(-50,-113) 4(0,-113) 5(50,-113) 6(100,-113) 7(150,-113) 8(150,113) 9(100,113) 10(50,113) 11(0,113) 12(-50,113) 13(-100,113) 14(-150,113)
  silkscreen extent -170,-65 170,65, body extent -171,-118 171,118, height 61
SOP-4 [mm] "光耦"
  rect 0.7x1.6 smd: 1(-1.27,-3.3)
  oval 0.7x1.6 smd: 2(1.27,-3.3) 3(1.27,3.3) 4(-1.27,3.3)
  silkscreen extent -2.25,-2.2 2.25,2.2, body extent -1.89,-3.55 1.96,3.45, height 2.1
SOT23 [mil]
  rect 50x40 smd: 1(45,-40) 2(-45,0) 3(45,40)
  silkscreen extent -45,-57 45,58, body extent -50,-57 47,57, height 39
SOT223 [mm]
  rect 1.1x2.15 smd: 1(-2.3,-3.1) 2(0,-3.1) 3(2.3,-3.1)
  rect 3.5x2.15 smd: 2(0,3.1)
  silkscreen extent -3.35,-1.63 3.35,1.63, body extent -3.25,-3.58 3.25,3.38, height 1.65
SOT-23 [mm]
  rect 1.2x0.9 smd: 1(1.2,-1) 2(-1.2,0) 3(1.2,1)
  silkscreen extent -0.65,-1.48 0.65,1.52, body extent -1.55,-1.55 1.45,1.45, height 1.3
SOT-23-6L [mm]
  rect 0.508x1.1 smd: 1(-0.95,-1.25) 2(0,-1.25) 3(0.95,-1.25) 4(0.95,1.25) 5(0,1.25) 6(-0.95,1.25)
  silkscreen extent -1.64,-1.27 1.66,1.27, body extent -1.38,-1.19 1.41,1.23, height 1.08
SW6*6 [mm]
  oval 1.524x1 hole 0.77: 1(-3.6,-2.3) 1(3.6,-2.3) 2(-3.6,2.3) 2(3.6,2.3)
  silkscreen extent -3.1,-3 2.9,3.1
SW12*17_PB86 [mm]
  round 1 hole 1: 0(-3.81,-5.08) 0(-3.81,10.16) 0(3.81,-5.08) 0(3.81,10.16)
  round 2 hole 0.6 slot 1.2 at 90 deg: 1(-3.81,-2.54) 4(3.81,-2.54)
  round 2 hole 0.6 slot 1.2 at 0 deg: 2(-3.81,2.54) 3(3.81,2.54)
  silkscreen extent -8.63,-6.36 8.63,10.9
TM024HDH26-V02 [mm]
  rect 3.2x2.5 smd: 0(0.95,-5.05) 0(0.95,5.05)
  oval 1.8x0.3 smd: 1(-0.95,-3.25) 2(-0.95,-2.75) 3(-0.95,-2.25) 4(-0.95,-1.75) 5(-0.95,-1.25) 6(-0.95,-0.75) 7(-0.95,-0.25) 8(-0.95,0.25) 9(-0.95,0.75) 10(-0.95,1.25) 11(-0.95,1.75) 12(-0.95,2.25) 13(-0.95,2.75) 14(-0.95,3.25)
  silkscreen extent -40.54,-21.39 19.72,21.33
TO252AA [mm]
  rect 2.2x0.95 smd: 1(3.275,-2.28) 3(3.275,2.28)
  rect 6.7x5.5 smd: 2(-3.275,0)
  silkscreen extent 0.47,-3.43 3.4,3.35, body extent -6.16,-3.27 3.78,3.27, height 2.39
TSSOP20 [mm]
  oval 0.45x2.1 smd: 1(-2.925,-3.45) 2(-2.275,-3.45) 3(-1.625,-3.45) 4(-0.975,-3.45) 5(-0.325,-3.45) 6(0.325,-3.45) 7(0.975,-3.45) 8(1.625,-3.45) 9(2.275,-3.45) 10(2.925,-3.45) 11(2.925,3.45) 12(2.275,3.45) 13(1.625,3.45) 14(0.975,3.45) 15(0.325,3.45) 16(-0.325,3.45) 17(-0.975,3.45) 18(-1.625,3.45) 19(-2.275,3.45) 20(-2.925,3.45)
  silkscreen extent -3.97,-3.57 4.01,2.21, body extent -3.31,-3.23 3.29,3.27, height 1.2
USB2*2 [mm] "卷口"
  rect 1.524x1.524 hole 0.92: 1(-1.25,-1)
  round 1.524 hole 0.92: 2(1.25,-1) 3(1.25,1) 4(-1.25,1)
  oval 2.6x3.8 hole 1.4 slot 2.3 at 90 deg: 5(-6.02,3.71) 6(6.02,3.71)
  silkscreen extent -6,-1.95 6,14.27

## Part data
Busy NG: library part LEDR
Busy1 NG1 OK1 Start1: library part MOS光耦
BZ1: library part Speaker
C1 C2 C3 C5 C6 C7 C8 C13 C14 C15 C16 C17 C18 C19 C20 C21 C22 C23 C24 C25 C26 C27 C28 C29 C31 C32 C33 C34 C35 C37 C38 C39 C40 C41 C42 C43 C44 C45 C46 C47 C48 C49 C50 C51 C52 C53 C54 C55 C56 C57 C58 C59 C60 C61 C62 C63 C64 C65 C66 C67 C68 C69 C70 C71 C72 C73 C74 C75 C76 C77: library part CAP, "无极电容"
C4 C9 C10 C11 C12 C30 C36: library part CAPACITOR, "Capacitor"
CN1: library part CON4, "接插件"
D1 D2: library part D, "二极管"
DZ1: library part DZ_s, "贴片稳压管"
DZ2: library part DZ, "稳压二极管"
G1 G2 G3 G4 T7 T8 T9 T10 T11 T12: library part J1
IC1: library part LM1117
IC2: library part 7805, "三端稳压"
IC3: library part LM324, "运放IC"
IC4: library part IC20Pin
J1 J3: library part Con10x2
J2 J4: library part Con5x2
L1 L2 L3 L7 L8 L9 L10 L11: library part L1
L4 L5: library part "INDUCTOR IRON"
L6: library part ACP3225
LCD1: library part SIP14, "jointbar"
OK: library part LEDG
P1: library part 1WDC_DC
POWER: library part LED-B
Q1 Q3 Q5 Q8 Q9 Q12 Q16 Q20: library part "MOSFET N", "场效应管"
Q2 Q4: library part PNP1, "三极管"
Q6 Q7 Q13 Q14 Q18 Q19: library part PMOS, "场效应管"
Q10 Q11 Q15 Q17: library part NPN1, "三极管"
R1 R2 R3 R4 R5 R6 R7 R8 R9 R10 R11 R12 R13 R14 R15 R16 R17 R18 R19 R21 R22 R24 R25 R26 R27 R28 R29 R30 R31 R32 R33 R34 R35 R36 R37 R38 R39 R40 R41 R42 R43 R44 R45 R46 R47 R48 R49 R50 R51 R52 R53 R54 R55 R56 R57 R58 R59 R60 R61 R62 R63 R64 R65 R66 R67 R68 R69 R70 R71 R72 R73 R75 R76 R77 R78 R79: library part R, "电阻"
R20 R23 R74: library part RES, "电阻"
RP1 RP2 RP3 RP4 RP5 RP6 RP7 RP8 RP9 RP10: library part RP-4
U1: "ARM Cortex-M4 32b MCU+FPU, 210DMIP, 512 kB Flash, 192+4 kB RAM, Camera, 82 I/Os, 100-pin LQFP, -40 to +85癈, Tray", Operating Frequency (Processor Speed)=168MHz
U2 U4: library part W25X16
U3: library part XL4007
U5: library part AD680AR
U6 U7 U8 U9 U10 U11: library part 6PIN
X1: library part ATX, "晶体振荡器"

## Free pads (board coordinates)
  round 1 hole 0.6: 3(65.75,29.41) 4(67.61,29.41) 5(69.46,29.41) 6(65.73,30.93) 7(65.71,32.67) 8(67.66,32.65) 9(69.5,32.69) 10(69.46,30.97) 11(67.61,31.08) 12(65.89,44.42) 13(65.8,42.92) 15(67.76,44.46) 16(67.73,42.9) 18(69.59,44.36) 19(69.54,42.86) 21(53.92,77.12) 22(53.92,75.3) 23(53.89,73.42) 24(55.84,77.12) 25(58.08,77.1) 26(55.84,75.23) 27(58,75.24) 28(55.92,73.39) 29(58.12,73.39)

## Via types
v1: diameter 0.5, hole 0.3, Top Layer to Bottom Layer, 444 vias
v2: diameter 0.6, hole 0.4, Top Layer to Bottom Layer, 412 vias
v3: diameter 0.8, hole 0.6, Top Layer to Bottom Layer, 8 vias

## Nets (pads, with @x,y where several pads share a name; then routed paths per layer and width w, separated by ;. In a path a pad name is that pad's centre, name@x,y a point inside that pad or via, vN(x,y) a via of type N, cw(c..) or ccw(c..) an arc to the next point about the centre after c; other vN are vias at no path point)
3.3V: C4.1 C6.2 C28.1 C40.1 C41.1 C42.1 C43.1 C44.1 C45.1 C46.1 C58.1 C61.2 C62.1 CN1.1 IC1.2 IC4.2 J1.1 J2.1 L1.1 LCD1.9 Q4.3 R2.2 R11.1 R25.2 R26.2 R66.2 R67.2 R69.1 R70.1 R71.2 R77.1 U1.6 U1.11 U1.19 U1.28 U1.50 U1.75 U1.100 U2.3 U2.7 U2.8 U4.8 | length 326.6
  Top Layer w0.3: v2(41.95,52) 42.02,52.07 LCD1.9@43.89,52.07
  Top Layer w0.45: v1(44.36,13.42) 51.723,13.42 v1(51.734,13.43) 58.25,13.43 58.79,12.89 61.58,12.89 65.67,16.98 65.67,18.49 J2.1@67.27,20.09
  Top Layer w0.5: v1(22.37,28.31) 22.38,28.3 31.35,28.3 32.23,27.42 40.92,27.42 41.89,28.39 45.29,28.39 v1(46.51,27.17)
  Top Layer w0.6: v3(16.85,52.13) 26.794,52.13 ; 26.874,52.13 v3@27.5,52.13 ; J2.1@66.98,19.8 J2.1@67.27,20.09 68.55,18.81 75.98,18.81 v2(76.77,18.02)
  power w0.3: v3(27.5,52.08) 27.5,47.87 28.956,46.414 28.956,46.342 29.278,46.02 29.35,46.02 29.76,45.61 v1(29.76,44.65)
  power w0.45: v3(27.5,52.08) 35.14,52.08 36.13,51.09 36.25,50.97 ; 36.052,51.012 v1(40.15,46.913) ; v1(44.36,13.42) v1@44.37,13.43
  power w0.5: v1(46.51,27.17) 46.51,25.14 49.45,22.2 49.45,20.314 51.094,18.67 54.3,18.67 55.43,19.8 66.98,19.8 J2.1@67.27,20.09
  power w0.6: v3(16.85,52.13) 16.85,44.47 ; v1(17.13,10.604) 15.31,12.424 15.31,18.15 16.6,19.44 v1(21.31,19.44) 22.37,20.5 v1(22.37,28.31) ; 21.4,44.47 16.85,44.47 ; 21.64,44.28 21.64,42.581 23.241,40.98 25.149,40.98 28.03,38.099 28.03,37.759 28.28,37.509 v1(28.28,37.28) ; v1(27.44,26.18) 25.29,28.33 v1(25.01,28.33) 24.99,28.31 v1(22.37,28.31) ; 36.052,51.012 36.13,51.09 37.94,52.9 39.91,52.9 40.81,52 v2(41.95,52) ; 16.85,44.47 16.85,35.88 13.76,35.88 J1.1@13.03,35.15 13.03,35.12 16.06,32.09 18.59,32.09 v1(22.37,28.31)
  Bottom Layer w0.3: J1.1@13.03,34.76 J1.1@13.03,35.15 ; L1.1@15.52,32.27 L1.1@15.595,32.27 ; R66.2@16.383,10.604 v1(17.13,10.604) 17.841,10.604 R67.2@17.855,10.591 ; v1(21.31,19.44) 21.33,19.46 R2.2@22.225,19.46 ; C42.1@21.331,38.439 21.331,38.218 22.528,37.022 U1.19@27.137,37.022 28.195,37.022 28.28,37.107 v1(28.28,37.28) ; 25.52,30.522 U1.6@27.137,30.522 ; 25.75,32.784 25.75,32.8 25.972,33.022 U1.11@27.137,33.022 ; v1(27.44,26.18) 27.451,26.169 C44.1@27.451,25.345 28.515,25.345 28.887,25.717 U1.100@28.887,26.272 ; v1(29.76,44.65) 29.72,44.69 29.34,44.31 29.336,44.31 29.336,43.654 29.887,43.103 U1.28@29.887,41.772 ; U1.50@40.887,41.772 40.887,44.061 C40.1@40.955,44.13 ; U1.75@42.637,28.022 45.779,28.022 C45.1@45.993,27.807 ; C45.1@45.984,27.8 45.984,27.676 46.49,27.17 v1(46.51,27.17) ; U2.3@50.187,13.355 50.262,13.43 v1(51.734,13.43) C61.2@52.66,13.43
  Bottom Layer w0.45: J1.1@13.03,34.76 L1.1@15.52,32.27 ; 22.384,27.813 C46.1@22.384,28.75 ; v1(25.01,28.33) 25.01,30.012 ; 25.122,30.92 25.52,30.522 25.01,30.012 ; 25.75,32.784 25.036,32.07 25.01,32.07 25.01,30.012 ; U4.8@34.544,13.08 34.544,12.156 36.03,10.67 37.269,10.67 ; R71.2@39.27,6.994 39.27,6.902 C62.1@37.839,6.902 R69.1@37.839,9.696 37.839,10.099 ; v1(40.15,46.913) 40.15,46.26 40.955,45.455 C40.1@40.955,44.44 ; U2.8@42.987,15.895 44.075,15.895 44.36,15.61 44.36,14.61 ; U2.7@43.625,14.625 44.345,14.625 44.36,14.61 ; IC4.2@73.32,15.295 74.695,15.295 ; 37.269,10.67 37.81,10.67 ; 37.269,10.67 37.839,10.099 ; 37.81,10.67 38.41,10.67 ; 37.81,10.67 37.839,10.641 37.839,10.099 ; 37.839,10.099 38.41,10.67 ; 38.41,10.67 40.97,10.67 41.55,11.25 43.973,11.25 44.36,11.637 v1(44.36,13.42) 44.36,14.61
  Bottom Layer w0.6: CN1.1@6,52.81 6.45,52.36 R26.2@9.085,52.36 9.084,52.434 10.06,53.41 11.86,53.41 12.17,53.1 12.17,50.86 ; R25.2@10.786,50.86 12.17,50.86 ; v3(16.85,52.13) Q4.3@16.043,51.324 15.564,51.324 15.1,50.86 12.17,50.86 ; v3(16.85,52.13) 17.124,52.13 R11.1@17.79,51.464 ; IC1.2@23.74,58.76 IC1.2@29.94,58.76 28.54,57.36 C4.1@28.54,53.66 27.516,52.636 C6.2@27.516,51.38 ; 33.96,51.72 36.412,51.72 37.981,50.151 R77.1@37.981,49.595 ; C58.1@41.034,51.495 41.539,52 v2(41.95,52) ; 74.695,15.295 75.84,16.44 75.84,17.02 76.77,17.95 v2(76.77,18.02) 76.77,22.144 C28.1@76.4,22.514
5V: BZ1.1 C9.1 C35.2 C75.1 D1.1 L3.1 L4.1 L6.2 LCD1.10 P1.1 R4.2 R12.2 R17.1 R27.2 U3.1 U3.2 | length 289.3
  Top Layer w0.3: LCD1.10@43.89,52.57 v3@46.39,52.57
  Top Layer w0.6: v1(5.05,21.16) 15.86,21.16 15.9,21.2 v1(15.93,21.17) ; v2(21.184,63.28) v2(22.54,63.28) 22.55,63.27 v2(29.66,63.27) ; v3(46.39,52.58) 46.98,52.58 50.93,48.63 v2(59.415,48.63) 82.38,48.63 v2(83.3,47.71) ; P1.1@81.684,50.43 P1.1@82.15,50.896
  power w0.5: v1(51.519,28.33) 52.639,29.45 58.48,29.45 58.485,29.445 59.29,30.25 59.29,32.99 60.51,34.21 60.51,47.535 v2(59.415,48.63)
  power w0.6: v1(5.05,21.16) 5.05,39.564 15.27,49.784 15.27,60.12 v2(17.03,61.88) ; C9.1@23.45,76.1 25.81,78.46 63.33,78.46 64.82,76.97 86.91,76.97 88.02,75.86 v1(88.02,75.09)
  Bottom Layer w0.4: v1(15.93,21.17) D1.1@15.93,19.788 16.277,19.44 R4.2@18.035,19.44 ; v1(51.519,28.33) 51.519,28.939 52.75,30.17 52.75,33.395 R27.2@53.576,34.22 ; R12.2@88.02,74.086 v1(88.02,75.09)
  Bottom Layer w0.6: v2(17.03,61.88) 17.86,62.71 17.86,63.29 ; L6.2@17.37,77.45 22.06,77.45 22.96,76.55 22.96,76.06 17.86,70.96 17.86,63.29 ; v2(21.184,63.28) 17.97,63.28 17.92,63.23 17.86,63.29 ; C9.1@23.07,76.44 23.45,76.06 27.814,76.06 29.402,74.472 29.402,73.008 31.03,71.38 31.03,66.59 ; U3.1@28.496,65.335 30.465,65.335 31.03,65.9 31.03,66.59 ; U3.2@28.496,66.605 31.015,66.605 31.03,66.59 ; v2(29.66,63.27) 34.993,63.27 38.983,59.28 42.69,59.28 46.41,55.56 46.41,52.56 v3(46.39,52.58) ; P1.1@82.15,50.896 82.15,47.74 82.18,47.71 v2(83.3,47.71)
5V-b: C34.2 P1.4 R61.2 RP6.1 RP6.2 RP6.3 RP6.4 Start1.1 | length 40.1
  Bottom Layer w0.3: RP6.1@73.51,67.52 RP6.2@74.46,67.52 RP6.3@75.26,67.52 RP6.4@76.21,67.52 85.229,67.52 R61.2@85.419,67.33 86.465,66.284 C34.2@86.465,65.43 83.984,65.43 P1.4@82.15,63.596
  Bottom Layer w0.6: v2(91.75,65.4) 91.76,65.4 91.76,48.65 94.26,46.15 Start1.1@94.65,46.15
12V: C12.1 C14.2 C25.2 IC2.3 IC3.4 pad.3 pad.4 pad.5 pad.6 pad.7 pad.8 pad.9 pad.10 pad.11 pad.12 pad.13 pad.15 pad.16 pad.18 pad.19 Q10.2 Q15.2 | length 81.5
  Top Layer w0.5: v3(48.33,48.63) 49.78,47.18 51.68,47.18 52.52,46.34 v3(52.52,45.64) v3(58.03,45.64) 67.11,45.64 v3(67.75,45.64) v3@67.74,45.65
  Top Layer w0.8: pad.12@65.89,44.42 67.11,45.64 67.12,45.65 v3@67.74,45.65
  Bottom Layer w0.3: Q15.2@67.65,30.14 67.65,42.415 Q10.2@67.7,42.465 67.75,42.515 v3(67.75,45.64)
  Bottom Layer w0.5: v3(48.33,48.63) 48.33,58.28 48.12,58.49 48.13,58.5 48.11,58.52 51.68,62.09 61.57,62.09 62.22,62.74 62.22,66.56 61.047,67.733 C12.1@60.31,67.733 62.885,70.308 IC2.3@62.885,72.09 ; v3(52.52,45.64) 52.52,45.48 52.518,45.478 C25.2@53.052,45.478 C25.2@53.108,45.478 ; IC3.4@55.94,48.31 IC3.4@56.42,48.31 57.18,48.31 58.03,47.46 v3(58.03,45.64)
AD-5V: C57.1 R17.2 R22.1 U1.36 | length 35.3
  Top Layer w0.3: v1(23.06,47.163) 23.18,47.283 35.357,47.283 35.48,47.16 35.42,47.1 v1(35.21,47.1)
  Bottom Layer w0.3: R17.2@19.887,61.378 19.875,61.366 R22.1@19.875,60.09 19.875,58.737 21.97,56.642 21.97,48.37 23.177,47.163 v1(23.06,47.163) ; U1.36@33.887,41.772 33.887,45.477 35.21,46.8 v1(35.21,47.1) 35.21,47.952 C57.1@35.193,47.969
AD-12V: C59.1 R14.2 R15.1 U1.35 | length 48
  Bottom Layer w0.3: R14.2@20.193,65.977 20.193,65.389 21.162,64.42 28.39,64.42 28.7,64.11 28.7,63.22 29.51,62.41 34.54,62.41 38.43,58.52 39.77,58.52 40.2,58.09 40.2,49.28 39.9,48.98 ; C59.1@32.338,47.969 R15.1@33.766,47.969 ; U1.35@33.387,41.772 33.387,47.59 R15.1@33.766,47.969 ; 40.14,49.21 39.75,48.82 34.617,48.82 R15.1@33.766,47.969
AD-Pin1: C19.2 RP3.1 U1.23 | length 107.4
  power w0.3: v1(29.66,39.07) 29.66,35.69 27.68,33.71 27.68,29.39 28.76,28.31 28.76,25 26.49,22.73 26.49,6.51 31.6,1.4 74.776,1.4 76.98,3.604 v1(76.98,3.95)
  Bottom Layer w0.3: C19.2@17.263,42.23 21.387,42.23 24.595,39.022 U1.23@27.137,39.022 v1@29.66,39.022 ; v1(76.98,3.95) 76.98,8.95 RP3.1@76.99,8.96
AD-Pin2: C20.2 RP3.2 U1.24 | length 140.2
  Top Layer w0.3: v1(7.13,39.61) v1(25.1,39.61)
  Bottom Layer w0.3: v1(7.13,39.61) 4.23,36.71 4.23,14.1 16.93,1.4 74.87,1.4 76.04,2.57 RP3.2@76.04,8.96 ; C20.2@17.22,43.633 21.047,43.633 25.158,39.522 U1.24@27.137,39.522
AD-Pin3: C21.2 RP3.4 U1.25 | length 94
  power w0.3: v1(33.77,40.022) 33.77,9.53 36.7,6.6 50.52,6.6 51.57,5.55 70.76,5.55 72.13,6.92 74.21,6.92 v1(74.27,6.86)
  Bottom Layer w0.3: C21.2@17.22,45.078 20.762,45.078 25.818,40.022 U1.25@27.137,40.022 v1(33.77,40.022) ; v1(74.27,6.86) 74.27,8.94 RP3.4@74.29,8.96
AD-Pin4: C22.2 RP3.3 U1.26 | length 134.1
  Top Layer w0.3: v1(12.86,43.36) v2@26.79,43.36
  Bottom Layer w0.3: v1(12.86,43.36) 5.51,36.01 5.51,27.91 6.2,27.22 6.2,14.43 17.83,2.8 72.47,2.8 75.25,5.58 75.25,8.95 RP3.3@75.24,8.96 ; C22.2@23.927,47.985 23.927,45.389 25.935,43.38 v2(26.79,43.38) v2@26.93,43.38 ; v2@26.86,43.45 v2@26.93,43.38 ; U1.26@28.887,41.772 28.887,42.313 27.82,43.38 v2@26.93,43.38
AD-Pin5: C23.2 RP4.1 U1.31 | length 106.8
  power w0.3: v2(27.52,46) 27.52,43.54 27.49,43.51 31.04,39.96 31.04,5.88 34.22,2.7 74.12,2.7 76.02,4.6 78.88,4.6 v1(81.53,7.25)
  Bottom Layer w0.3: C23.2@26.627,47.969 26.627,46.833 27.46,46 v2(27.52,46) 30.19,46 31.387,44.803 U1.31@31.387,41.772 ; v1(81.53,7.25) RP4.1@81.53,8.99
AD-Pin6: C24.2 RP4.2 U1.32 | length 102.1
  power w0.3: v1(29.55,46.62) 29.55,46.603 29.54,46.593 29.563,46.57 29.727,46.733 32.43,44.03 32.43,6.95 35.29,4.09 73.75,4.09 75.65,5.99 78.86,5.99 80.24,7.37 v1(80.25,7.37)
  Bottom Layer w0.3: C24.2@28.055,47.969 28.055,47.275 28.71,46.62 v1(29.55,46.62) 30.42,46.62 31.887,45.153 U1.32@31.887,41.772 ; v1(80.25,7.37) 80.25,7.38 80.58,7.71 RP4.2@80.58,8.99
AD-Pin7: C26.2 RP4.3 U1.33 | length 91.6
  Top Layer w0.3: v2(32.07,46.35) 32.07,46.25 v2@32.22,46.1
  power w0.3: v2(32.07,46.35) 32.08,46.35 34.31,44.12 34.31,41.97 35.21,41.07 35.21,12.83 38.95,9.09 50.51,9.09 51.97,7.63 69.482,7.63 70.162,8.31 75.628,8.31 76.578,7.36 v1(78.41,7.36)
  Bottom Layer w0.3: C26.2@29.482,47.969 30.311,47.14 30.78,47.14 31.57,46.35 v2(32.07,46.35) ; v2@32.1,46.33 32.387,46.043 U1.33@32.387,41.772 ; v1(78.41,7.36) 78.98,7.36 79.78,8.16 RP4.3@79.78,8.99
AD-Pin8: R44.1 U1.34 | length 7.4
  Bottom Layer w0.3: R44.1@30.91,47.969 31.759,47.12 32.47,47.12 32.887,46.703 U1.34@32.887,41.772
AD-Vdd: C53.2 R47.2 R52.1 U1.16 | length 70.2
  Top Layer w0.254: v2@69.21,37.45 69.23,37.47 v2(69.23,37.63)
  Top Layer w0.3: v2(17.77,34.88) 18.07,34.58 25.09,34.58 v2(25.59,35.08) ; v2@25.59,34.964 v2(25.59,35.08) ; v2(69.23,37.63) 58.53,37.63 57.05,36.15 38.332,36.15 37.482,35.3 25.87,35.3 25.65,35.08 v2(25.59,35.08)
  power w0.3: v2@25.59,35.02 v2(25.59,35.08)
  Bottom Layer w0.254: v2(69.23,37.63) 70.84,37.63 71.18,37.29 78.383,37.29 78.833,36.84 80.434,36.84 R52.1@81.19,37.596 81.19,39.316 R47.2@81.145,39.36
  Bottom Layer w0.3: C53.2@17.253,35.1 17.473,34.88 17.523,34.93 17.573,34.88 v2(17.77,34.88) ; v2(25.59,35.08) v2@25.59,35.04 ; U1.16@27.137,35.522 26.072,35.522 v2@25.59,35.04 ; v2@25.59,35.04 25.59,35.029 25.531,34.97 25.526,34.976 v2@25.59,35.04
AD-Vpp: C52.2 R60.2 R63.1 U1.15 | length 73
  Top Layer w0.3: v2(17.76,33.3) 26.87,33.3 27.38,33.81 29.91,33.81 v2(30.09,33.63) v2@30.07,33.61 ; v2(39.83,30.11) 47.33,30.11 48.2,29.24 60.13,29.24 62.31,27.06 78.68,27.06 v1(78.69,27.05)
  Bottom Layer w0.3: C52.2@17.253,33.656 17.317,33.72 17.76,33.277 v2(17.76,33.3) ; U1.15@27.137,35.022 28.708,35.022 30.09,33.64 v2(30.09,33.63) 30.09,33.597 31.437,32.25 38.32,32.25 38.91,31.66 38.91,31.03 v2(39.83,30.11) ; v1(78.69,27.05) 80.305,27.05 R63.1@81.13,27.875 ; R63.1@80.96,28.046 R63.1@81.13,27.875 ; R60.2@81.136,29.23 81.13,29.225 R63.1@81.13,27.875
AD-VS: C54.2 R33.2 R35.1 U1.17 | length 72.8
  Top Layer w0.3: v2(17.89,36.43) 23.98,36.43 v2(24.66,35.75) ; v2(36.78,36.05) 37.41,36.68 56.73,36.68 58.3,38.25 v2(63.028,38.25)
  Bottom Layer w0.3: C54.2@17.253,36.544 17.367,36.43 v2(17.89,36.43) ; v2(24.66,35.75) 24.66,35.803 24.878,36.022 U1.17@27.137,36.022 36.887,36.022 36.858,36.05 v2(36.78,36.05) ; v2(63.028,38.25) 63.028,43.408 63.62,44 63.62,46.69 64.92,47.99 67.35,47.99 67.7,48.34 67.7,54.51 67.44,54.77 65.955,54.77 R33.2@65.2,55.525
  Bottom Layer w0.6: R35.1@65.03,58.305 65.03,55.695 R33.2@65.2,55.525
AD-VS-b: C55.2 R31.2 R34.1 U1.18 | length 88.8
  Top Layer w0.3: v2@36.74,37.22 56.47,37.22 58.23,38.98 v2(63.66,38.98) ; v2@59.62,57.8 v2(73.13,57.8)
  Bottom Layer w0.3: C55.2@17.263,37.831 17.47,37.831 17.941,37.36 21.09,37.36 21.928,36.522 U1.18@27.137,36.522 36.005,36.522 v2(36.74,37.256) ; R34.1@58.68,58.274 59.42,58.274 ; v2(59.42,57.83) 59.42,58.274 ; R31.2@60.217,58.274 59.42,58.274 ; v2(63.66,38.98) 63.66,43.14 64.29,43.77 64.29,46.38 65.23,47.32 69.67,47.32 72.15,49.8 72.15,52.396 73.13,53.376 v2(73.13,57.8)
AGND: C19.1 C20.1 C21.1 C22.1 C23.1 C24.1 C26.1 C47.2 C48.2 C52.1 C53.1 C54.1 C55.1 L2.1 U1.20 | length 39.8
  Top Layer w0.3: v1(15.602,37.179) 16.183,37.76 v2(22.93,37.76) ; v1(19.79,48.69) 22.45,48.69 22.47,48.67 v1@22.64,48.84
  Bottom Layer w0.3: C21.1@15.56,45.078 15.602,45.035 v1(15.602,37.179) C53.1@15.602,35.1 C52.1@15.602,33.656 ; C21.1@15.569,45.078 15.648,45.078 17.021,46.451 L2.1@17.211,46.451 17.551,46.451 v1(19.79,48.69) ; v1(22.66,48.83) 22.66,48.92 23.335,49.595 23.885,49.595 C22.1@23.927,49.636 24.723,48.84 25.847,48.84 C23.1@26.627,49.62 C24.1@28.055,49.62 C26.1@29.482,49.62 ; v2(22.93,37.76) 22.96,37.76 23.198,37.522 U1.20@27.137,37.522
BL: Q5.1 R24.1 U1.61 | length 31.8
  Top Layer w0.3: v2(37.488,53.77) 41.81,53.77 41.82,53.78 v2(42,53.78) ; v2(39.61,40.23) 40.1,40.72 v2(43.57,40.72)
  Bottom Layer w0.3: R24.1@37.488,53.229 v2(37.488,53.77) Q5.1@37.488,54.745 ; v2@39.49,40.3 39.49,35.94 40.408,35.022 U1.61@42.637,35.022 ; v2(42,53.78) 43.61,52.17 43.57,52.13 v2(43.57,40.72)
Boot0: J1.3 R1.2 U1.94 U8.1 | length 30.8
  Top Layer w0.3: v2@19.192,29.25 21.78,29.25 22.07,28.96 v2@25.85,28.96 ; v2(25.85,29) v2@25.85,29.12
  Bottom Layer w0.3: J1.3@13.03,32.61 13.643,32.61 14.763,31.49 15.412,31.49 ; U8.1@15.41,30.49 15.41,31.488 15.412,31.49 ; v2(19.192,29.24) 18.79,29.24 18.18,29.85 18.18,31.09 17.78,31.49 15.412,31.49 ; v2(25.85,29) 25.85,27.97 26.39,27.43 31.54,27.43 31.887,27.083 U1.94@31.887,26.272 31.887,20.987 R1.2@31.097,20.197
Busy: RP7.3 RP8.2 U1.63 | length 112.7
  Top Layer w0.3: v2(41.26,34.3) 42.74,34.3 43.03,34.59 47.37,34.59 48.35,35.57 57.3,35.57 58.75,37.02 71.83,37.02 73.73,38.92 83.205,38.92 84.03,39.746 95.036,39.746 95.43,40.14 v2(96.62,40.14) ; v2(69.98,66.13) 79.28,66.13 80.03,66.88 v2(93.55,66.88)
  Bottom Layer w0.3: v2(41.26,34.3) 41.232,34.3 41.51,34.022 U1.63@42.637,34.022 ; RP8.2@69.98,64.95 v2(69.98,66.13) ; v2(93.55,66.88) 93.63,66.8 93.63,50.17 96.99,46.81 96.99,42.19 96.62,41.82 v2(96.62,40.14)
